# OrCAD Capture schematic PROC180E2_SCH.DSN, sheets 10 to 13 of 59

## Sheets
10 21. SOC RESET - 1: size C; title: SOC  RESET - 1
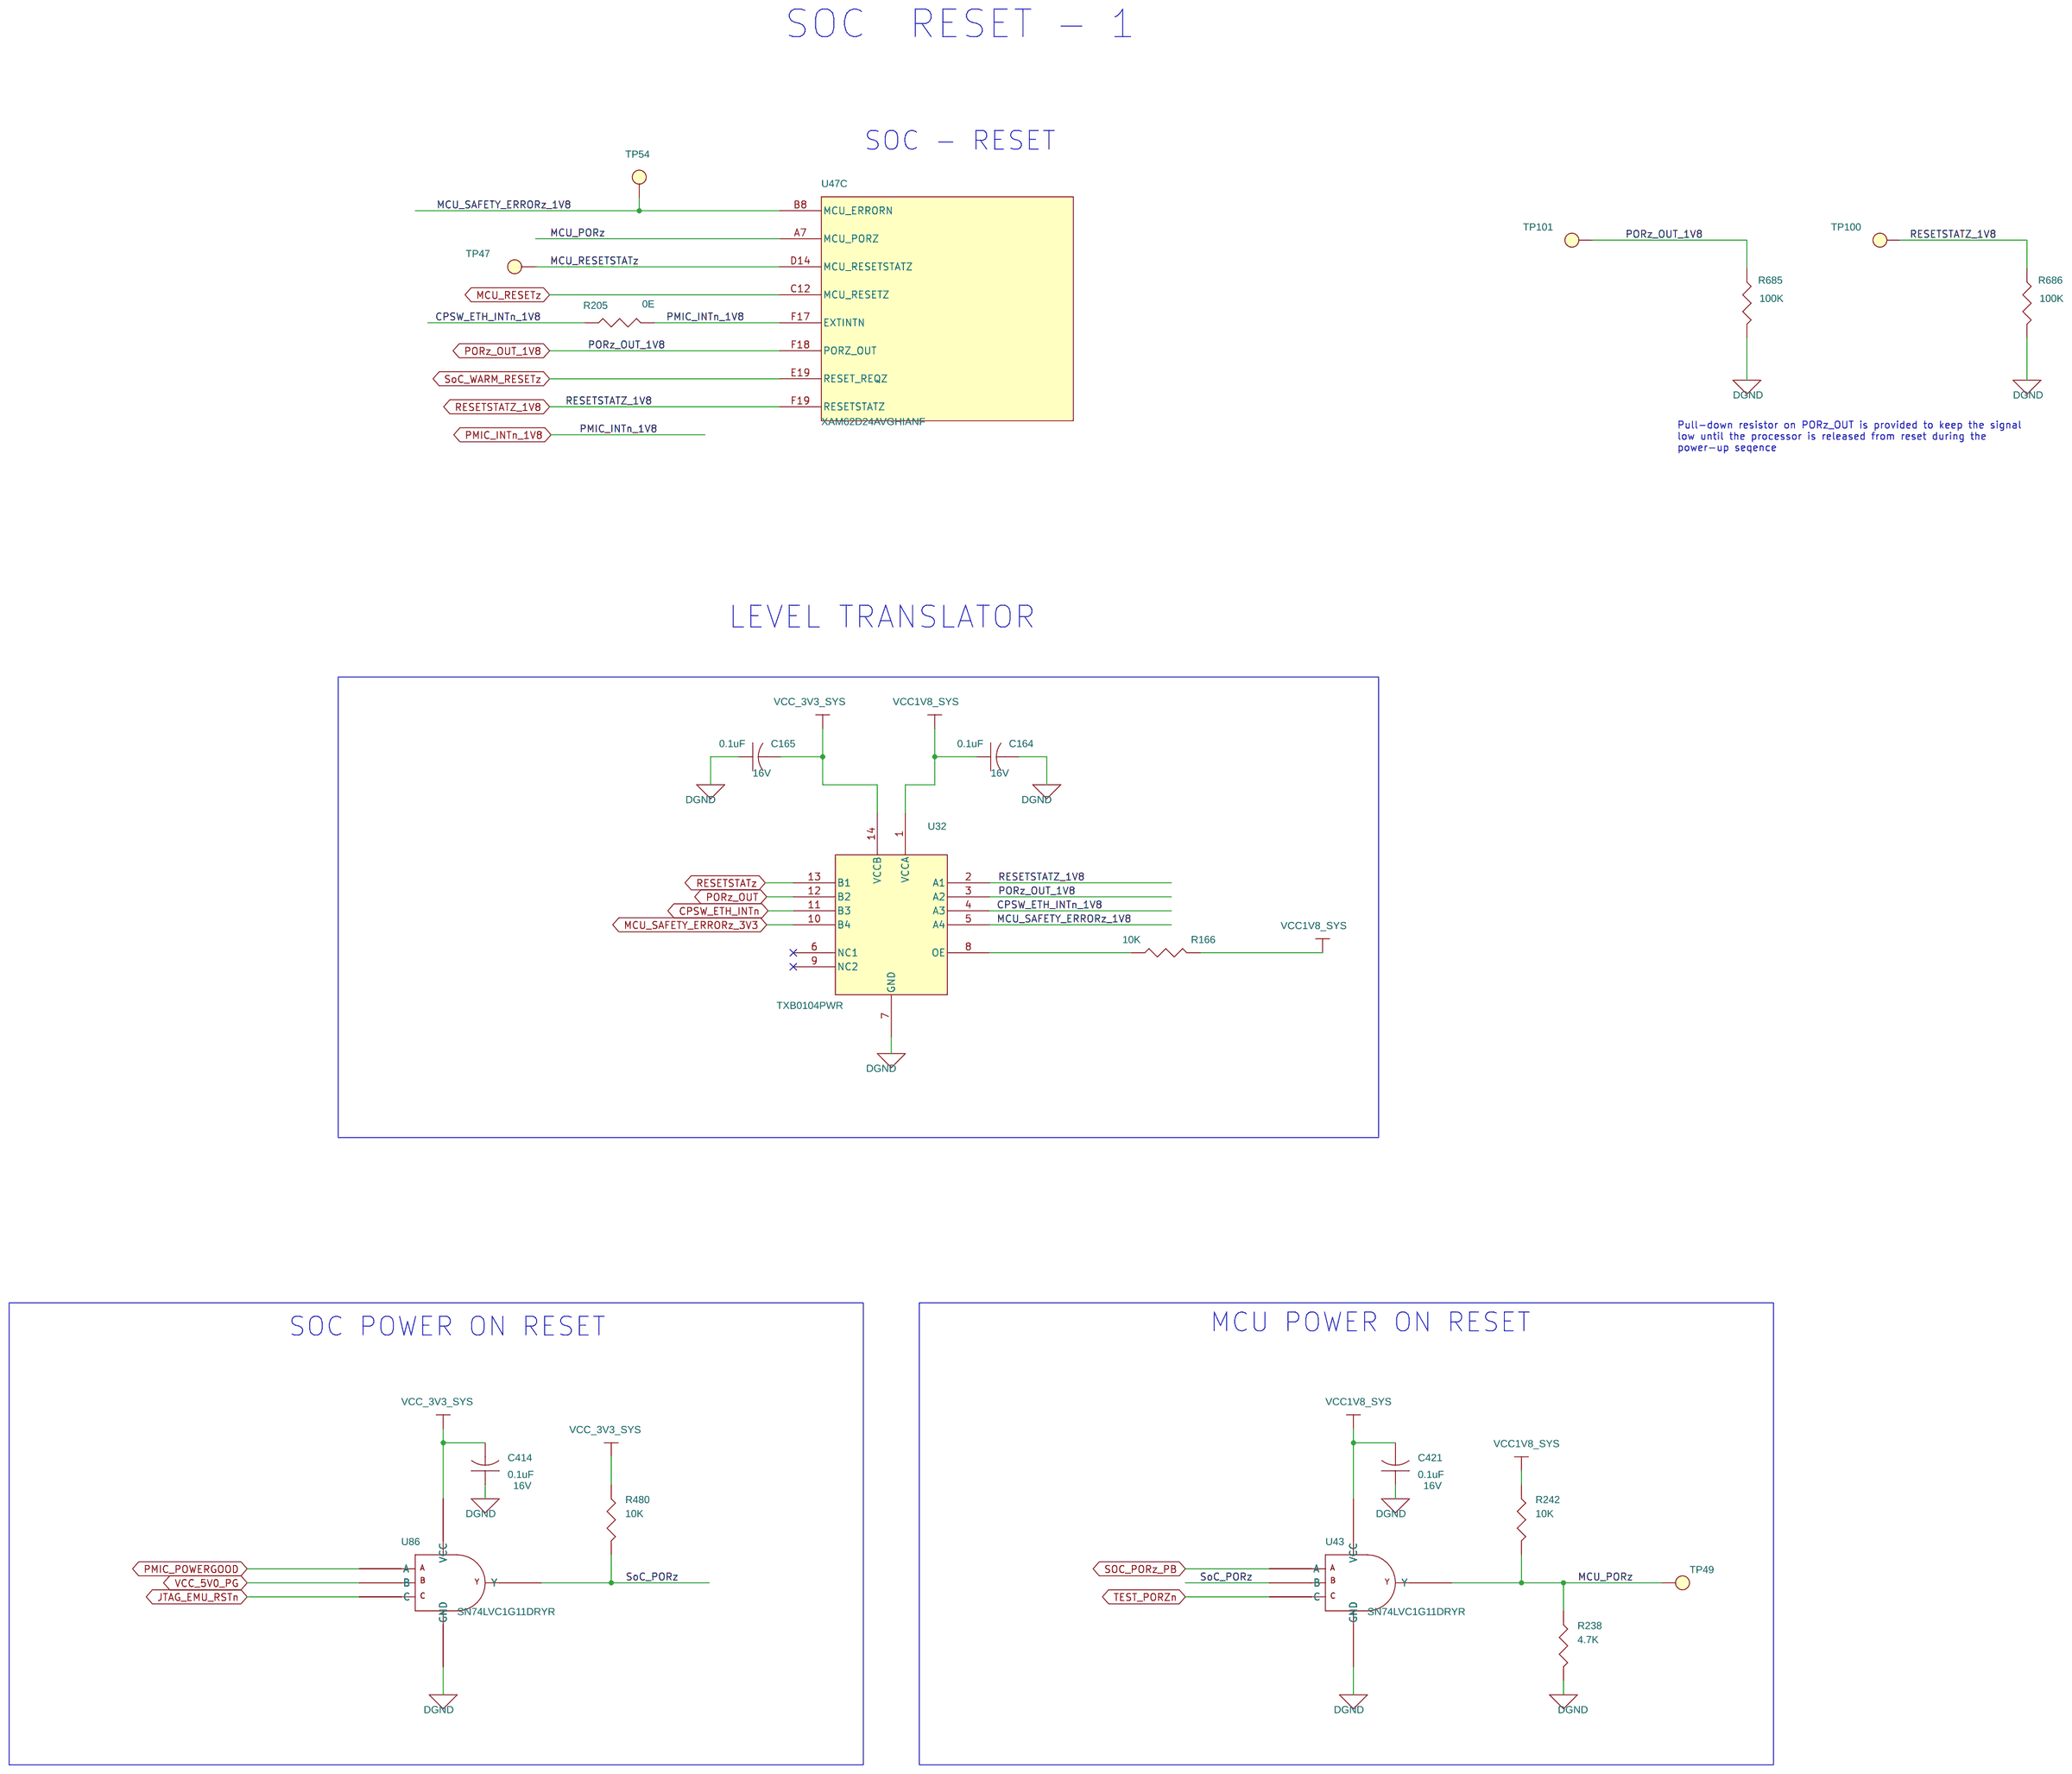
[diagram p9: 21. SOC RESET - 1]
11 28. SOC PERIPHERALS 1: size C; title: SOC PERIPHERALS 1
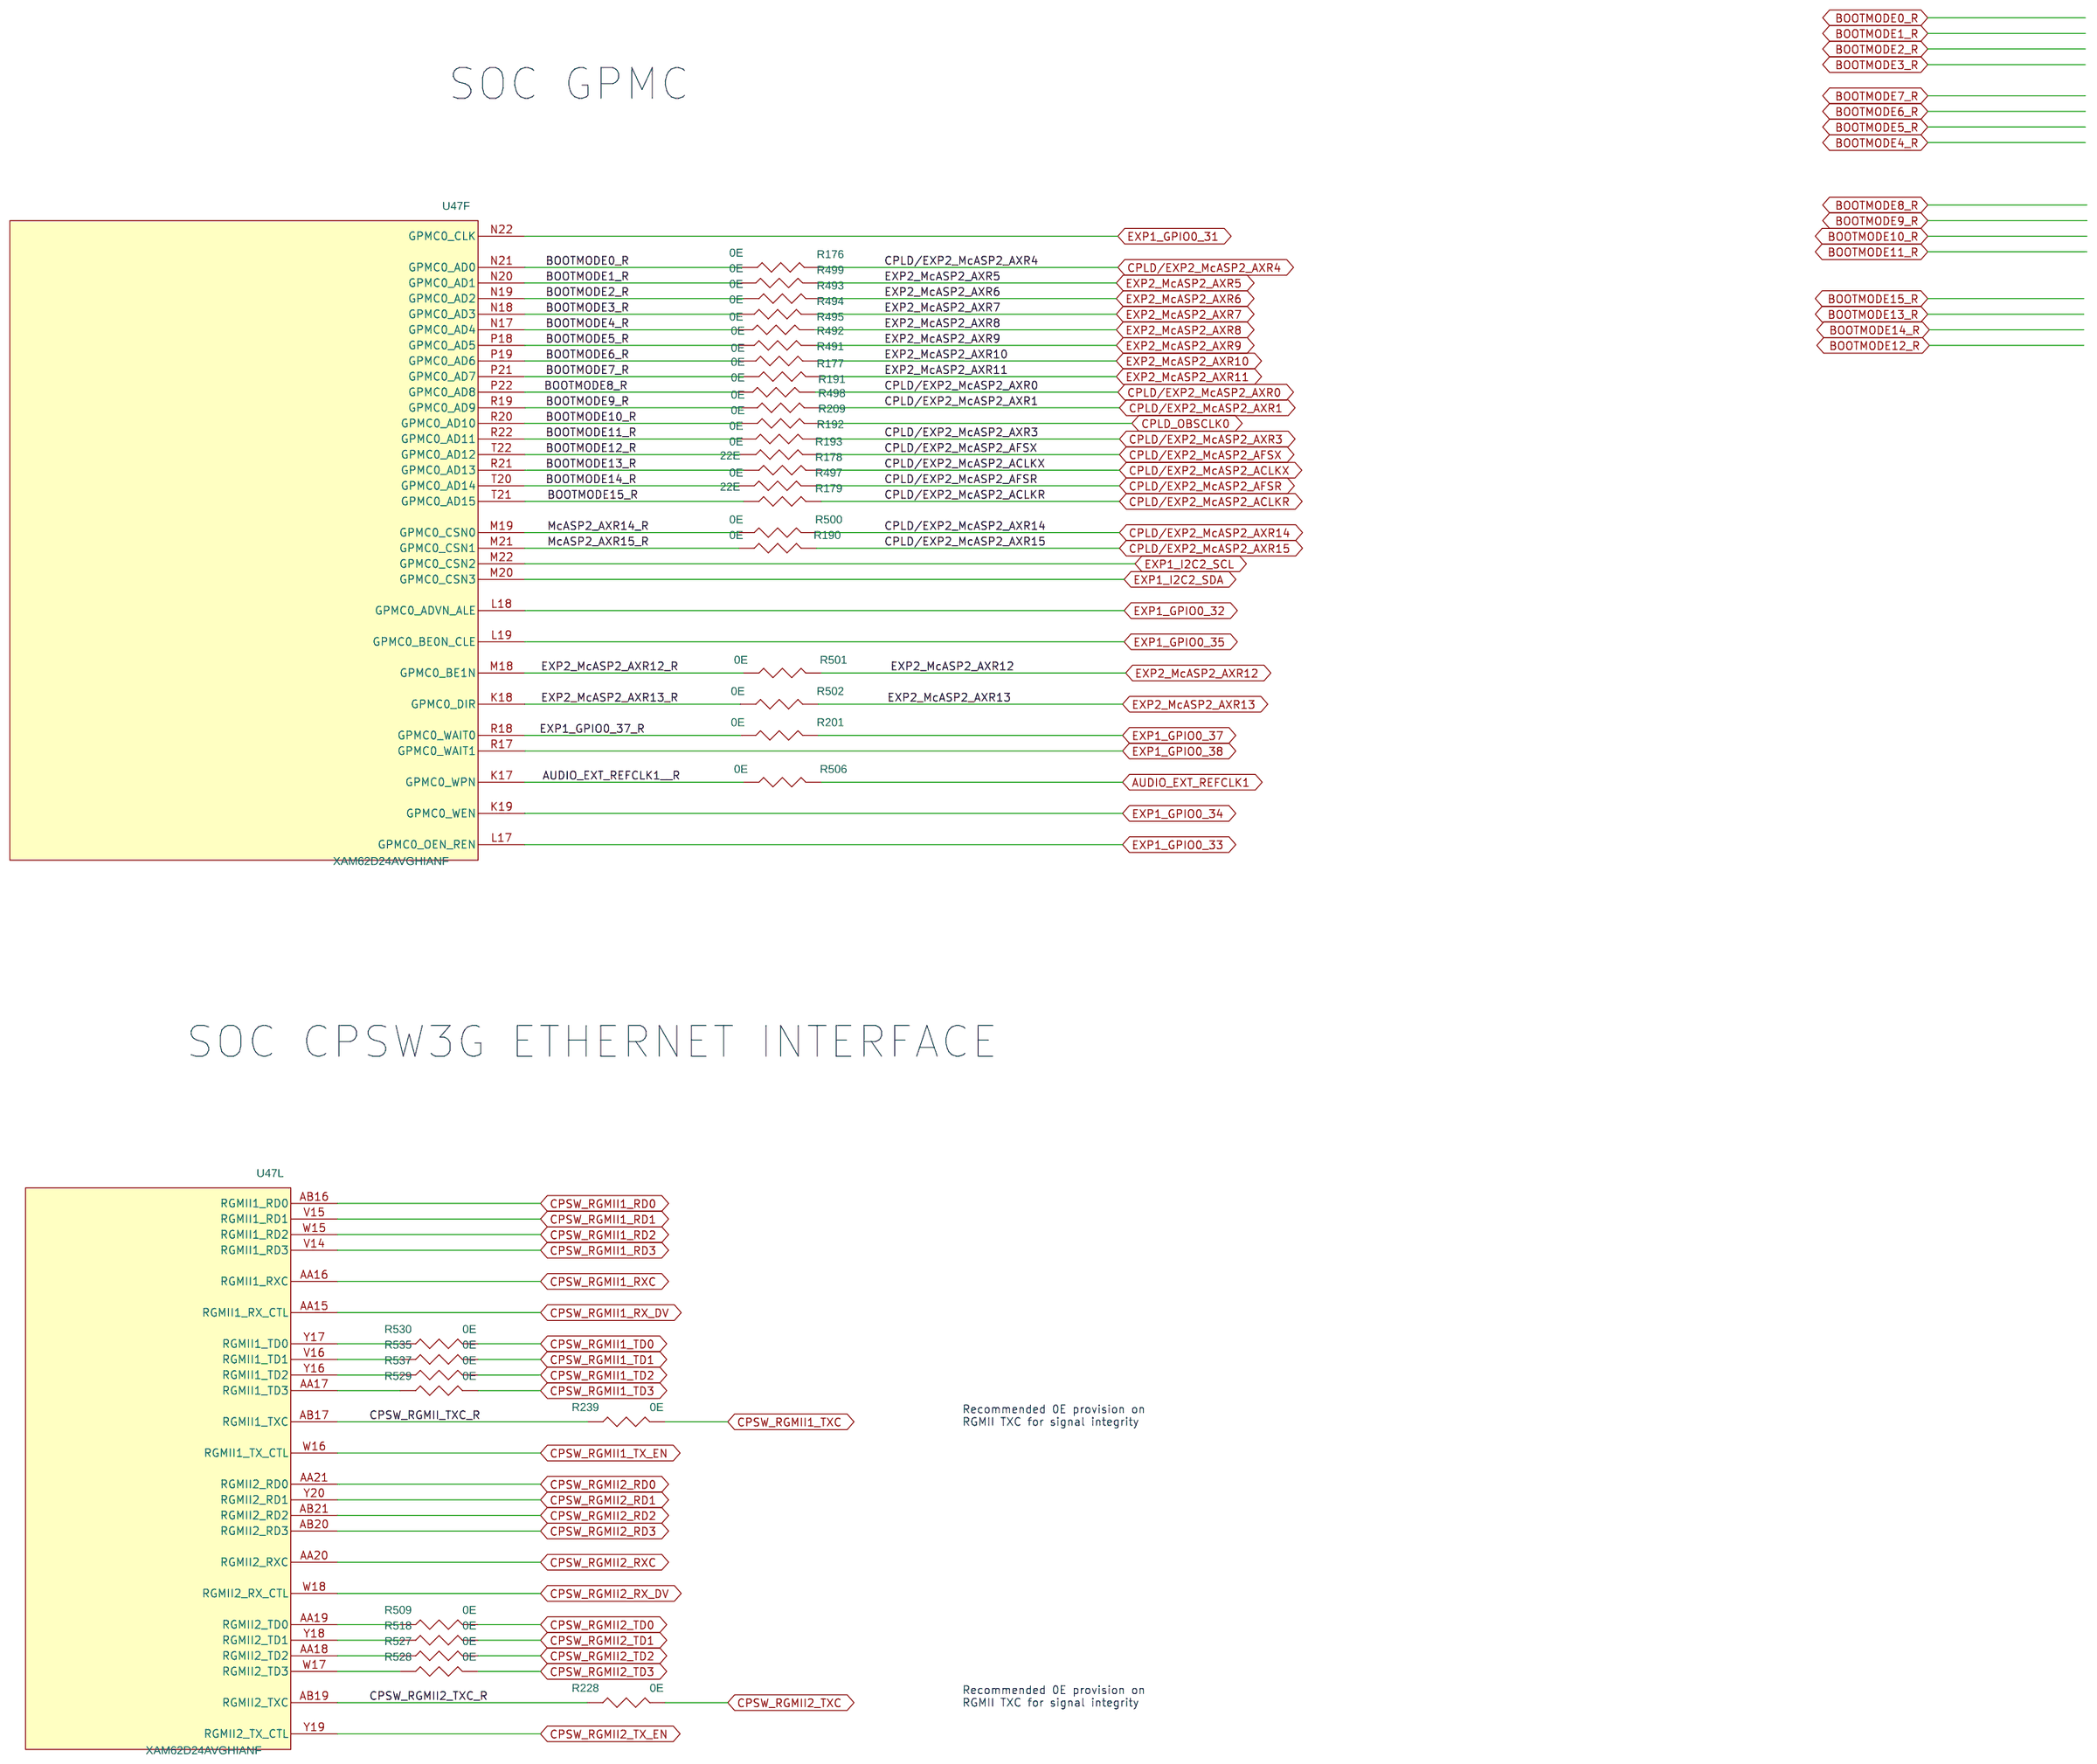
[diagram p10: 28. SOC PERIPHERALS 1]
12 11. USB TYPE-C POWER CONNECTOR: size C; title: USB TYPE-C POWER CONNECTOR
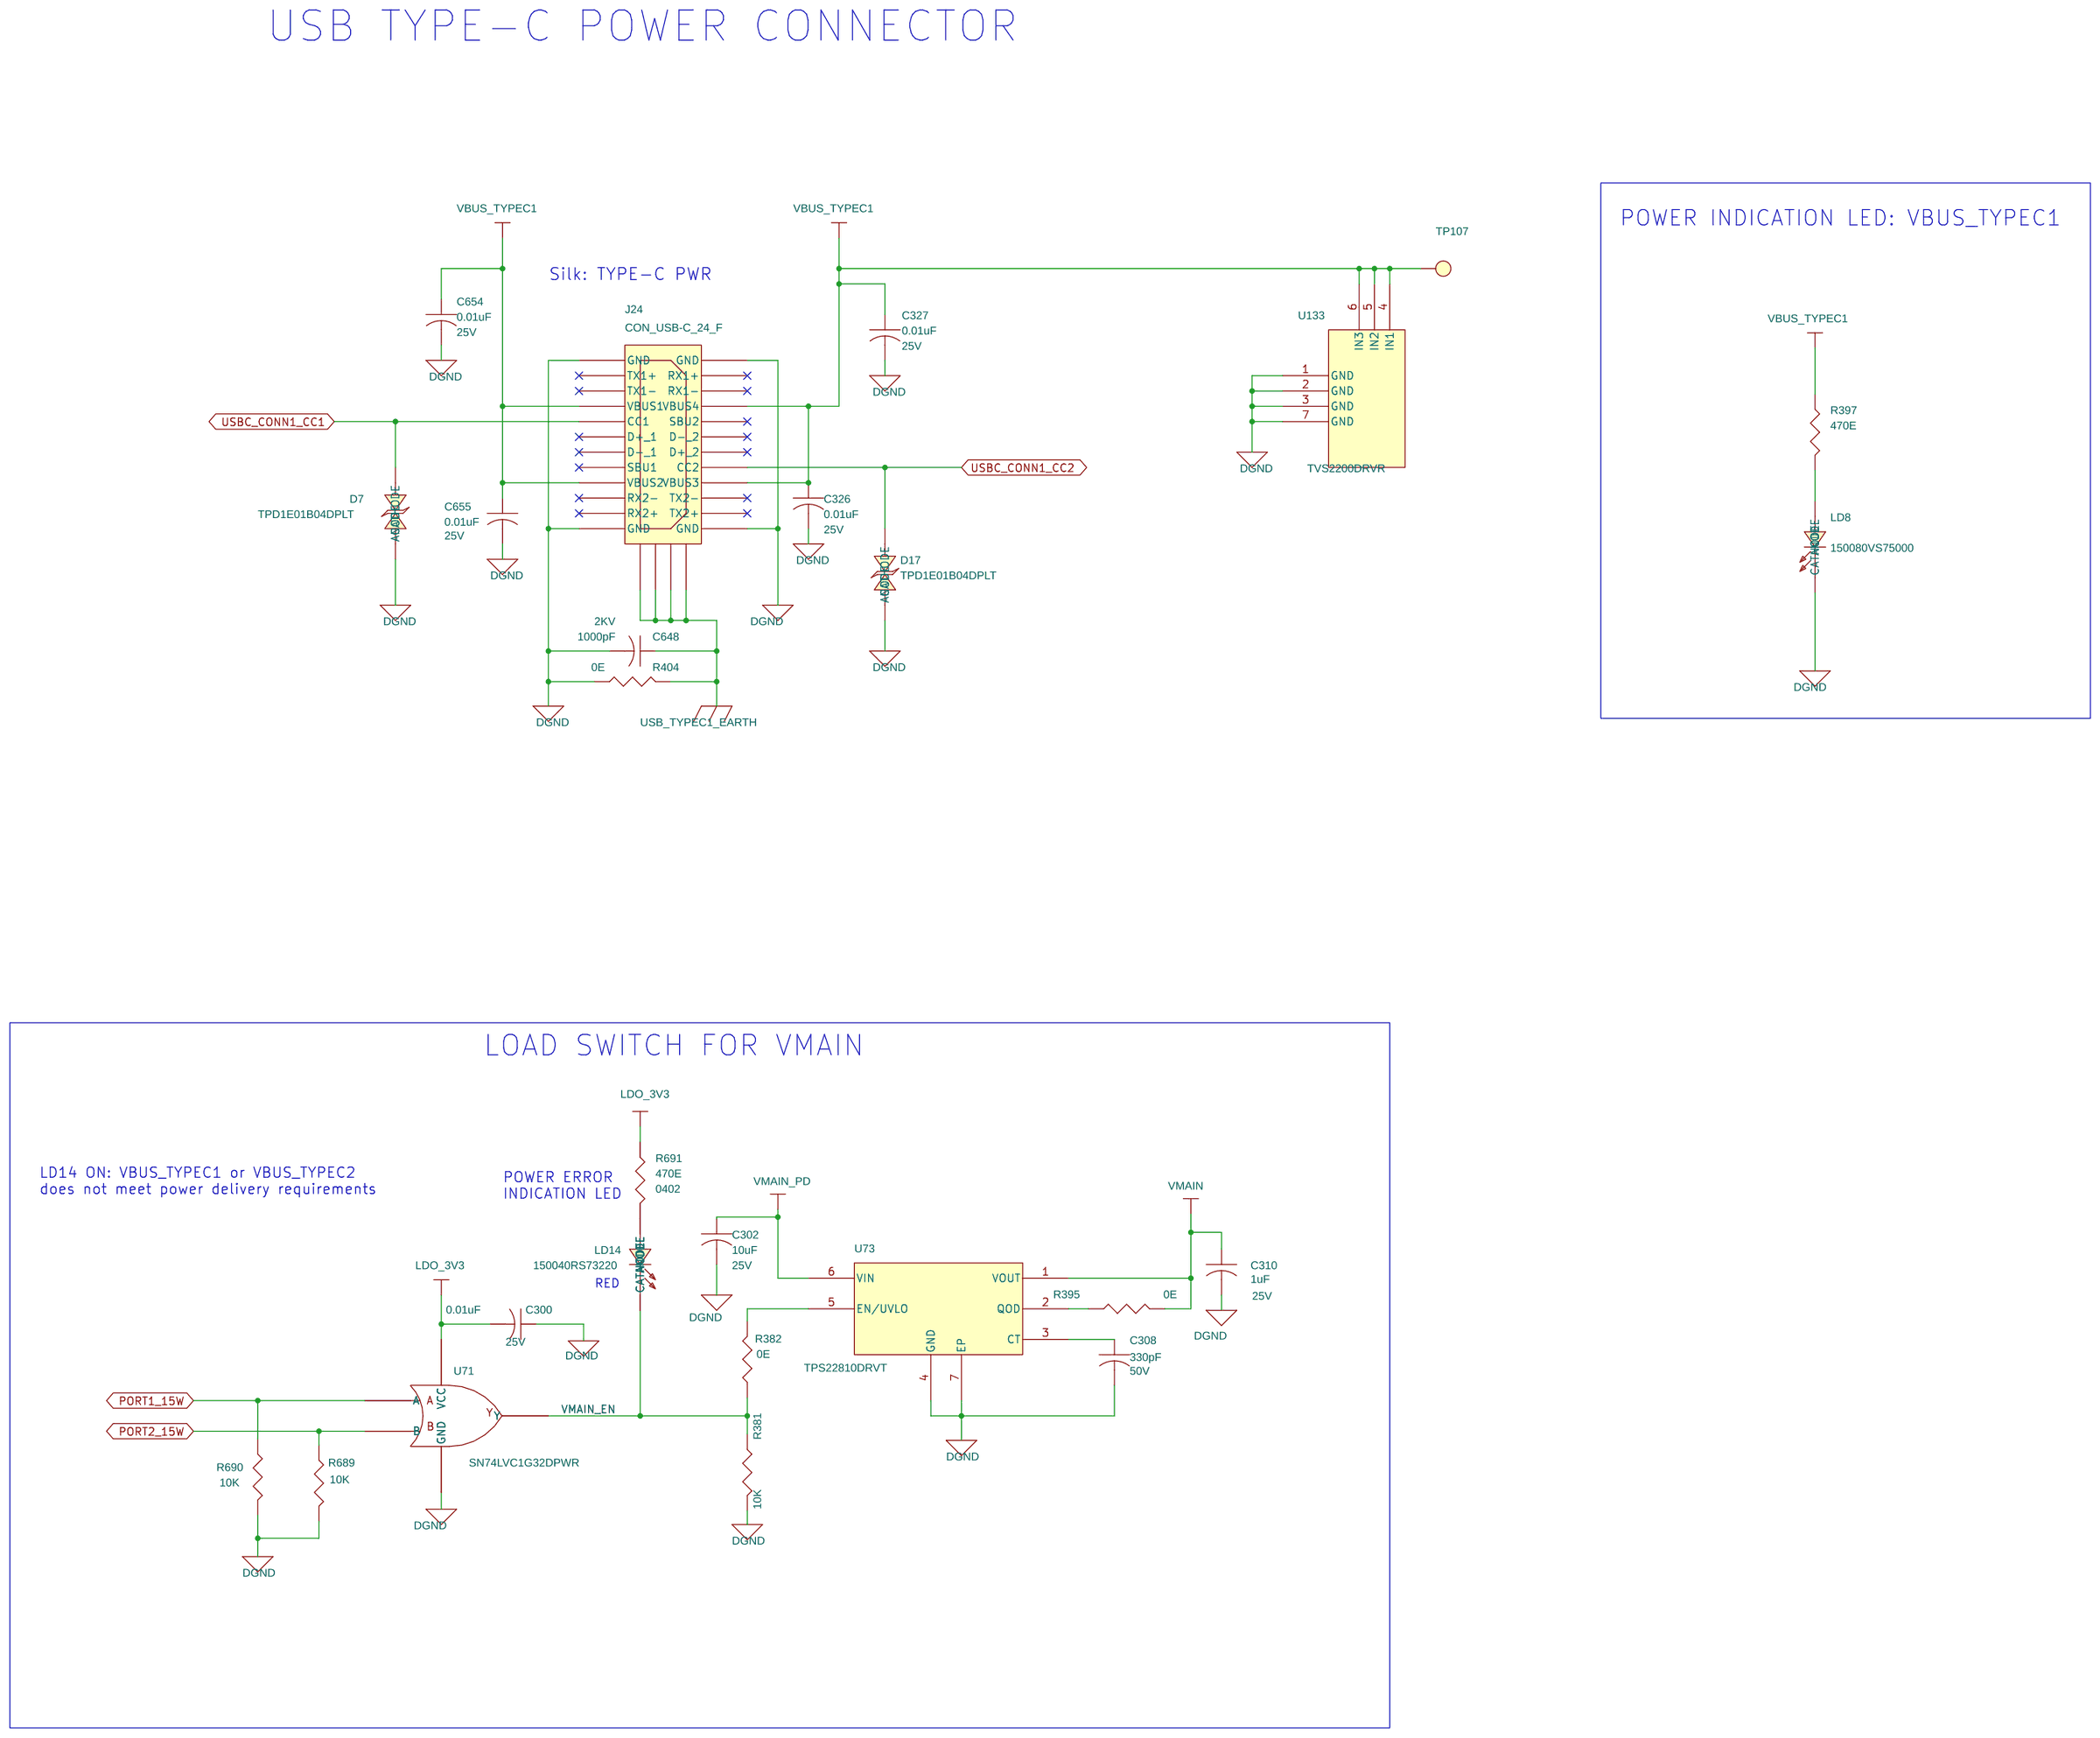
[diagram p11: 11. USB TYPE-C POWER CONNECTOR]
13 18. SOC POWER SUPPLIES - DECAPS: size C; title: SOC POWER SUPPLIES - DECAPS 2
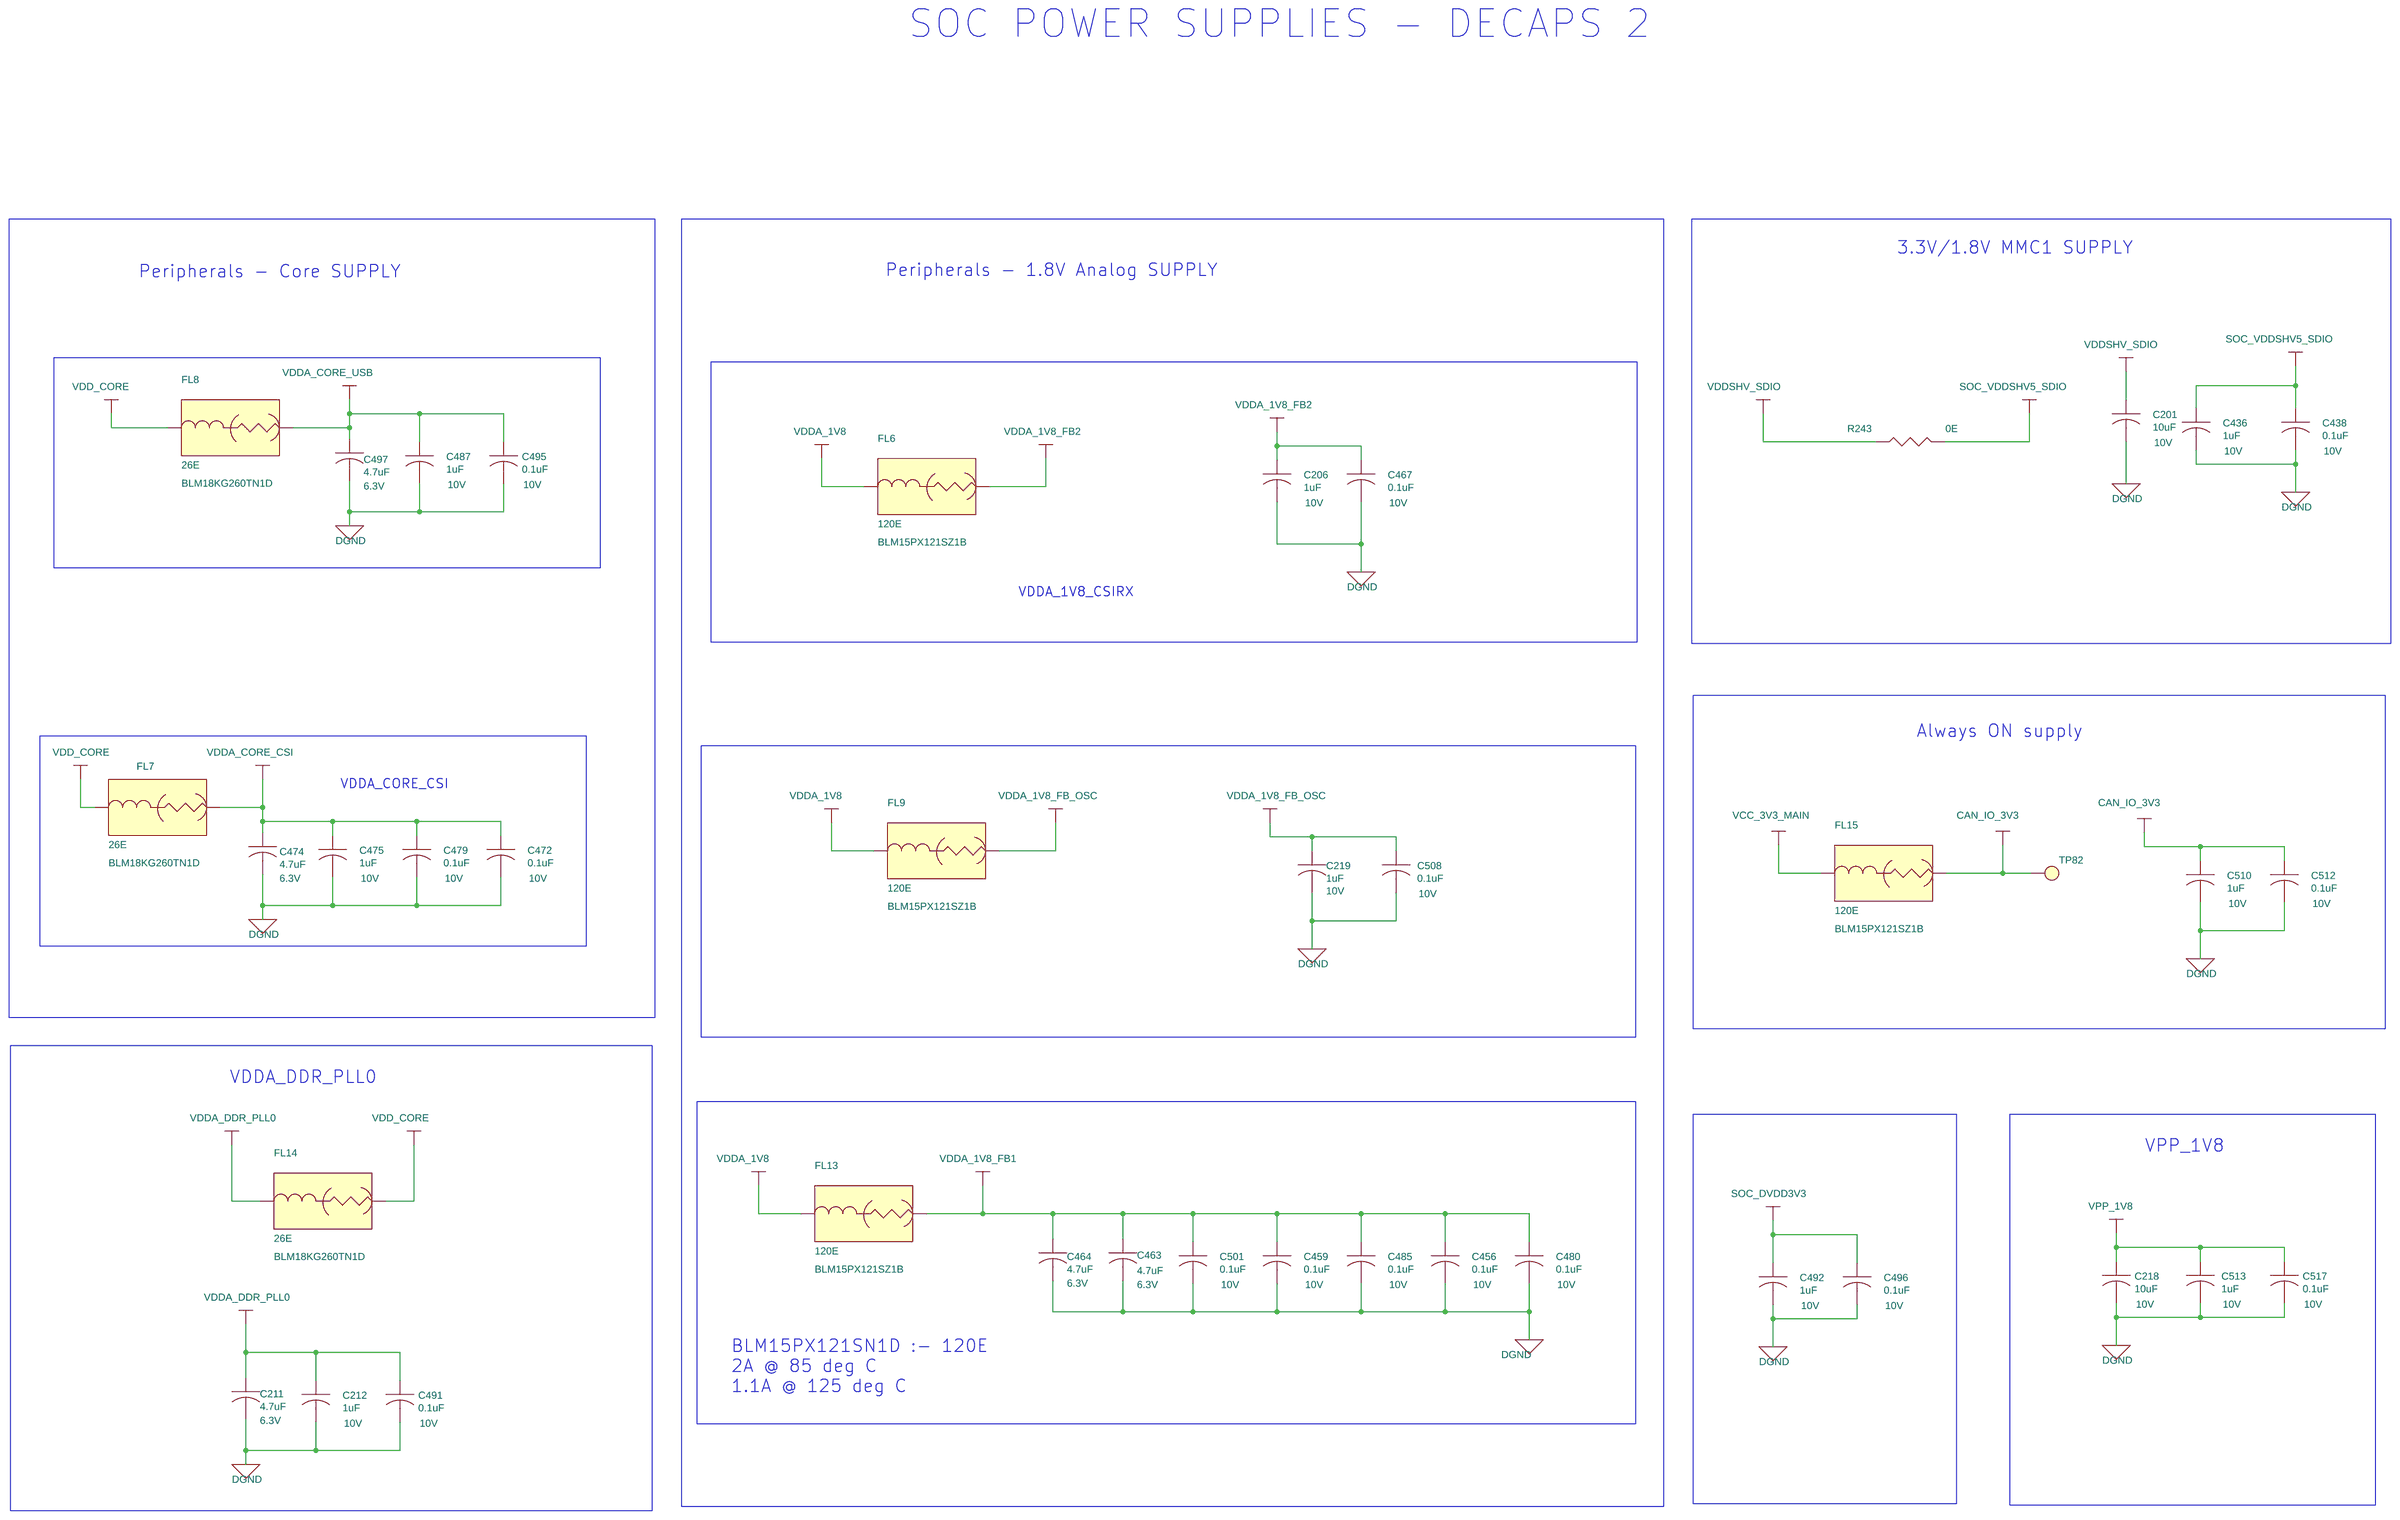
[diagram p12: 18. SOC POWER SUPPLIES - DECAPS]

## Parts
sheet 11. USB TYPE-C POWER CONNECTOR
C300  0.01uF  [CAP0201_0-5]
C302  10uF  [CAP0603_1]
C308  330pF  [CAP0402_0-75]
C310  1uF  [CAP0402_0-75]
C326  0.01uF  [CAP0201_0-5]
C327  0.01uF  [CAP0201_0-5]
C648  1000pF  [CAP1206_1-75]
C654  0.01uF  [CAP0201_0-5]
C655  0.01uF  [CAP0201_0-5]
D7  TPD1E01B04DPLT  [DIO_DFN0201_0-4]
D17  TPD1E01B04DPLT  [DIO_DFN0201_0-4]
J24  CON_USB-C_24_F  [CON_USBC24_2012670_S_R_S_3-9]
LD8  150080VS75000  [LED_150080VS75000_80X50_SMD_0-8]
LD14  150040RS73220  [LED_150040GS73220_40X20_SMD_0-4]
R381  10K  [RES0201_0-5]
R382  0E  [RES0201_0-5]
R395  0E  [RES0603_0-75]
R397  470E  [RES0402_0-5]
R404  0E  [RES0603_0-75]
R689  10K  [RES0201_0-5]
R690  10K  [RES0201_0-5]
R691  470E  [RES0402_0-5]
TP107  TP20_SMD  [TP20_SMD]
U71  SN74LVC1G32DPWR  [X2SON5_TLV7021_30X30_0-4]
U73  TPS22810DRVT  [SON6_25-59_85X85_0-8]
U133  TVS2200DRVR  [SON6_25-59_85X85_0-8]
sheet 18. SOC POWER SUPPLIES - DECAPS
C201  10uF  [CAP0402_1]
C206  1uF  [CAP0201_0-5]
C211  4.7uF  [CAP0201_0-5]
C212  1uF  [CAP0201_0-5]
C218  10uF  [CAP0402_1]
C219  1uF  [CAP0201_0-5]
C436  1uF  [CAP0201_0-5]
C438  0.1uF  [CAP0201_0-5]
C456  0.1uF  [CAP0201_0-5]
C459  0.1uF  [CAP0201_0-5]
C463  4.7uF  [CAP0201_0-5]
C464  4.7uF  [CAP0201_0-5]
C467  0.1uF  [CAP0201_0-5]
C472  0.1uF  [CAP0201_0-5]
C474  4.7uF  [CAP0201_0-5]
C475  1uF  [CAP0201_0-5]
C479  0.1uF  [CAP0201_0-5]
C480  0.1uF  [CAP0201_0-5]
C485  0.1uF  [CAP0201_0-5]
C487  1uF  [CAP0201_0-5]
C491  0.1uF  [CAP0201_0-5]
C492  1uF  [CAP0201_0-5]
C495  0.1uF  [CAP0201_0-5]
C496  0.1uF  [CAP0201_0-5]
C497  4.7uF  [CAP0201_0-5]
C501  0.1uF  [CAP0201_0-5]
C508  0.1uF  [CAP0201_0-5]
C510  1uF  [CAP0201_0-5]
C512  0.1uF  [CAP0201_0-5]
C513  1uF  [CAP0201_0-5]
C517  0.1uF  [CAP0201_0-5]
FL6  120E  [EMIFIL_BLM15A_0402_0-6]
FL7  26E  [EMIFIL_BLM18K_0603]
FL8  26E  [EMIFIL_BLM18K_0603]
FL9  120E  [EMIFIL_BLM15A_0402_0-6]
FL13  120E  [EMIFIL_BLM15A_0402_0-6]
FL14  26E  [EMIFIL_BLM18K_0603]
FL15  120E  [EMIFIL_BLM15A_0402_0-6]
R243  0E  [RES0402_0-5]
TP82  TP20_SMD  [TP20_SMD]
sheet 21. SOC RESET - 1
C164  0.1uF  [CAP0201_0-5]
C165  0.1uF  [CAP0201_0-5]
C414  0.1uF  [CAP0201_0-5]
C421  0.1uF  [CAP0201_0-5]
R166  10K  [RES0201_0-5]
R205  0E  [RES0201_0-5]
R238  4.7K  [RES0201_0-5]
R242  10K  [RES0201_0-5]
R480  10K  [RES0201_0-5]
R685  100K  [RES0201_0-5]
R686  100K  [RES0201_0-5]
TP47  TP20_SMD  [TP20_SMD]
TP49  TP20_SMD  [TP20_SMD]
TP54  TP20_SMD  [TP20_SMD]
TP100  TP20_SMD  [TP20_SMD]
TP101  TP20_SMD  [TP20_SMD]
U32  TXB0104PWR  [TSSOP14_25-59_205X180_1-2]
U43  SN74LVC1G11DRYR  [SON6_SN74LVC2G17_40X60_0-6]
U47  XAM62D24AVGHIANF  [FBGA484_31-49_710X710_2-7]  (sections A,B,C,D,E,F,G,H,I,J,K,L,M,N,O,P,Q)
U86  SN74LVC1G11DRYR  [SON6_SN74LVC2G17_40X60_0-6]
sheet 28. SOC PERIPHERALS 1
R176  0E  [RES0402_0-5]
R177  0E  [RES0402_0-5]
R178  22E  [RES0402_0-5]
R179  22E  [RES0402_0-5]
R190  0E  [RES0402_0-5]
R191  0E  [RES0402_0-5]
R192  0E  [RES0402_0-5]
R193  0E  [RES0402_0-5]
R201  0E  [RES0402_0-5]
R209  0E  [RES0402_0-5]
R228  0E  [RES0201_0-5]
R239  0E  [RES0201_0-5]
R491  0E  [RES0402_0-5]
R492  0E  [RES0402_0-5]
R493  0E  [RES0402_0-5]
R494  0E  [RES0402_0-5]
R495  0E  [RES0402_0-5]
R497  0E  [RES0402_0-5]
R498  0E  [RES0402_0-5]
R499  0E  [RES0402_0-5]
R500  0E  [RES0402_0-5]
R501  0E  [RES0402_0-5]
R502  0E  [RES0402_0-5]
R506  0E  [RES0402_0-5]
R509  0E  [RES0201_0-5]
R518  0E  [RES0201_0-5]
R527  0E  [RES0201_0-5]
R528  0E  [RES0201_0-5]
R529  0E  [RES0201_0-5]
R530  0E  [RES0201_0-5]
R535  0E  [RES0201_0-5]
R537  0E  [RES0201_0-5]

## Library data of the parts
C300 C326 C327 C654 C655 = CAP: CAP CERAMIC 0.01uF 25V 10% X5R AUTO 0201; Chkd/date: MANIRAJA/311221; Crtd /date: ALVY/301221; Custom_Duty: 15%; Customs_HS_Code: 85322990; Distributor_name: MOUSER; Distributor_part_number: 81-GRT033R61E103KE1D; Footprint Path: Y:\MIS_DATABASE\Library\ALTIUM_TOOL\PCB_FOOTPRINTS\Altium_Footprint_Lib.PcbLib; Height: 0.33MM; Library Path: Y:\MIS_DATABASE\Library\ALTIUM_TOOL\SCHEMATICS_PARTS\MS_DISCRETE_Library.schlib; Mfr_name: MURATA; Mfr_part_number: GRT033R61E103KE01D; Mistral Part No: 120021120019-R; Package: 0201; Part_type: CAPACITORS\CERAMIC; Project: AM62Q_SKEVM_BRD; RoHS: RoHS; Temperature: -55°C+85°C; Tolerance: 10%; Voltage: 25V; Wattage: NA; Weight: 0.33mg; Datasheet: Y:\MIS_DATABASE\DATASHEETS\CAPACITORS\GRT033R61E103KE01.PDF
C302 = CAP: CAP CERAMIC 10uF 25V 20% X5R AUTO 0603; Chkd/date: PRADEEP/130623; Crtd /date: PRADEEP/130623; Custom_Duty: 15%; Customs_HS_Code: 85322990; Distributor_name: NA; Distributor_part_number: NA; Footprint Path: Y:\MIS_DATABASE\Library\ALTIUM_TOOL\PCB_FOOTPRINTS\Altium_Footprint_Lib.PcbLib; Height: 1.00MM; Library Path: Y:\MIS_DATABASE\Library\ALTIUM_TOOL\SCHEMATICS_PARTS\MS_DISCRETE_Library.schlib; Mfr_name: MURATA; Mfr_part_number: GRT188R61E106ME13; Mistral Part No: 120022060023-R; Package: 0603; Part_type: CAPACITORS\CERAMIC; Project: AM62P_SK; RoHS: RoHS; Temperature: -55°C+85°C; Tolerance: 20%; Voltage: 25V; Wattage: NA; Weight: 2mg; Datasheet: Y:\MIS_DATABASE\DATASHEETS\CAPACITORS\GRT188R61E106ME13.PDF
C308 = CAP: CAP CERAMIC 330pF 50V 5% C0G(NP0) AUTO 0402; Chkd/date: MANIRAJA/250221; Crtd /date: ALVY/240221; Custom_Duty: 15%; Customs_HS_Code: 85322990; Distributor_name: MOUSER; Distributor_part_number: 81-GRT1555C1H331JA2D; Footprint Path: Y:\MIS_DATABASE\Library\ALTIUM_TOOL\PCB_FOOTPRINTS\Altium_Footprint_Lib.PcbLib; Height: 0.55MM; Library Path: Y:\MIS_DATABASE\Library\ALTIUM_TOOL\SCHEMATICS_PARTS\MS_DISCRETE_Library.schlib; Mfr_name: MURATA; Mfr_part_number: GRT1555C1H331JA02D; Mistral Part No: 120019050019-R; Package: 0402; Part_type: CAPACITORS\CERAMIC; Project: TI_DRA821 SK EVM BRD; RoHS: RoHS; Temperature: -55°C+125°C; Tolerance: 5%; Voltage: 50V; Wattage: NA; Weight: 3.1mg; Datasheet: Y:\MIS_DATABASE\DATASHEETS\CAPACITORS\GRT1555C1H331JA02.PDF
C310 = CAP: CAP CERAMIC 1uF 25V 10% X6S AUTO 0402; Chkd/date: MANIRAJA/270520; Crtd /date: ALVY/260520; Custom_Duty: 15%; Customs_HS_Code: 85322990; Distributor_name: DIGIKEY; Distributor_part_number: 490-18215-1-ND; Footprint Path: Y:\MIS_DATABASE\Library\ALTIUM_TOOL\PCB_FOOTPRINTS\Altium_Footprint_Lib.PcbLib; Height: 0.60MM; Library Path: Y:\MIS_DATABASE\Library\ALTIUM_TOOL\SCHEMATICS_PARTS\MS_DISCRETE_Library.schlib; Mfr_name: MURATA; Mfr_part_number: GRT155C81E105KE13D; Mistral Part No: 120020050024-R; Package: 0402; Part_type: CAPACITORS\CERAMIC; Project: DARE_ECU_MCB; RoHS: RoHS; Temperature: -55°C+105°C; Tolerance: 10%; Voltage: 25V; Wattage: NA; Weight: 1.6mg; Datasheet: Y:\MIS_DATABASE\DATASHEETS\CAPACITORS\GRT155C81E105KE13.PDF
C648 = CAP: CAP CERAMIC 1000pF 2KV 10% X7R 1206; Chkd/date: SHREESHAIL/291106; Crtd /date: MAZHAR/281106; Custom_Duty: 15%; Customs_HS_Code: 85322990; Distributor_name: DIGIKEY; Distributor_part_number: 478-2956-1-ND; Footprint Path: Y:\MIS_DATABASE\Library\ALTIUM_TOOL\PCB_FOOTPRINTS\Altium_Footprint_Lib.PcbLib; Height: 1.52MM; Library Path: Y:\MIS_DATABASE\Library\ALTIUM_TOOL\SCHEMATICS_PARTS\MS_DISCRETE_Library.schlib; Mfr_name: AVX CORPORATION; Mfr_part_number: 1206GC102KAT1A; Mistral Part No: 120015080006-R; Package: 1206; Part_type: CAPACITORS\CERAMIC; Project: ADR1B; RoHS: RoHS; Temperature: -55°C+125°C; Tolerance: 10%; Voltage: 2KV; Wattage: NA; Weight: 16.2mg; Datasheet: Y:\MIS_DATABASE\DATASHEETS\CAPACITORS\AVX_HV-MLC.PDF
D7 D17 = DIODE_TVS_DUAL: DIODE 1CH ESD PROTECTION FOR USB TYPE-C AND THUNDERBOLT3 X2SON2; Chkd/date: MANIRAJA/230920; Crtd /date: ALVY/230920; Custom_Duty: 15%; Customs_HS_Code: 85412900; Distributor_name: DIGIKEY; Distributor_part_number: 296-44484-1-ND; Footprint Path: Y:\MIS_DATABASE\Library\ALTIUM_TOOL\PCB_FOOTPRINTS\Altium_Footprint_Lib.PcbLib; Height: 0.32MM; Library Path: Y:\MIS_DATABASE\Library\ALTIUM_TOOL\SCHEMATICS_PARTS\MS_DISCRETE_Library.schlib; Mfr_name: TEXAS INSTRUMENTS; Mistral Part No: 130020090037-R; Package: X2SON2; Part_type: DIODE\TVS; Project: AM64X_SKEVM; RoHS: RoHS; Temperature: -40°C+125°C; Tolerance: NA; Voltage: NA; Wattage: NA; Weight: 0.2mg; Datasheet: Y:\MIS_DATABASE\DATASHEETS\DISCRETES\DIODES\TPD1E01B04.PDF
J24 = CON_USB-C_24_1240183621: CON USB-C TYPE 24POS FEMALE RT SMD; Chkd/date: MANIRAJA/050618; Crtd /date: ALVY/040618; Custom_Duty: 24%; Customs_HS_Code: 85369090; Distributor_name: DIGIKEY; Distributor_part_number: WM17992CT-ND; Footprint Path: Y:\MIS_DATABASE\Library\ALTIUM_TOOL\PCB_FOOTPRINTS\Altium_Footprint_Lib.PcbLib; Height: 3.86MM; Library Path: Y:\MIS_DATABASE\Library\ALTIUM_TOOL\SCHEMATICS_PARTS\MS_CONNECTOR_Library.schlib; Mfr_name: MOLEX; Mfr_part_number: 2012670005; Mistral Part No: 150018060002-R; Package: SMD; Part_type: CONNECTOR\USB; Project: TI_J7SVB_USB_ADD-ON-CARD; RoHS: RoHS; Temperature: -40°C+105°C; Tolerance: NA; Voltage: NA; Wattage: NA; Weight: 0.686g; Datasheet: Y:\MIS_DATABASE\DATASHEETS\CONNECTORS\2012670X.PDF
LD8 = DIODE_LED: DIODE LED BRIGHT GREEN SMD; Chkd/date: MANIRAJA/180820; Crtd /date: ALVY/180820; Custom_Duty: 24%; Customs_HS_Code: 85439000; Distributor_name: DIGIKEY; Distributor_part_number: 732-4986-1-ND; Footprint Path: Y:\MIS_DATABASE\Library\ALTIUM_TOOL\PCB_FOOTPRINTS\Altium_Footprint_Lib.PcbLib; Height: 0.80MM; Library Path: Y:\MIS_DATABASE\Library\ALTIUM_TOOL\SCHEMATICS_PARTS\MS_OPTO_Library.schlib; Mfr_name: WURTH ELECTRONICS; Mistral Part No: 130020080012-R; Package: SMD; Part_type: OPTO\LED; Project: AM64x_EVM_BRD; RoHS: RoHS; Temperature: -40°C+85°C; Tolerance: NA; Voltage: NA; Wattage: NA; Weight: 10mg; Datasheet: Y:\MIS_DATABASE\DATASHEETS\DISCRETES\LEDS\150080VS75000.PDF
LD14 = DIODE_LED: DIODE LED RED SMD; Chkd/date: MANIRAJA/100920; Crtd /date: ALVY/100920; Custom_Duty: 24%; Customs_HS_Code: 85439000; Distributor_name: DIGIKEY; Distributor_part_number: 732-13422-1-ND; Footprint Path: Y:\MIS_DATABASE\Library\ALTIUM_TOOL\PCB_FOOTPRINTS\Altium_Footprint_Lib.PcbLib; Height: 0.35MM; Library Path: Y:\MIS_DATABASE\Library\ALTIUM_TOOL\SCHEMATICS_PARTS\MS_OPTO_Library.schlib; Mfr_name: WURTH ELECTRONICS; Mistral Part No: 130020090020-R; Package: SMD; Part_type: OPTO\LED; Project: AM64X_SKEVM; RoHS: RoHS; Temperature: -40°C+85°C; Tolerance: NA; Voltage: NA; Wattage: NA; Weight: 29.3mg; Datasheet: Y:\MIS_DATABASE\DATASHEETS\DISCRETES\LEDS\150040RS73220.PDF
R166 R242 R381 R480 R689 R690 = RESISTOR: RES 10K 1/20W 5% 0201; Chkd/date: MANIRAJA/050517; Crtd /date: MANIRAJA/050517; Custom_Duty: 15%; Customs_HS_Code: 85332119; Distributor_name: DIGIKEY; Distributor_part_number: 311-10KNCT-ND; Footprint Path: Y:\MIS_DATABASE\Library\ALTIUM_TOOL\PCB_FOOTPRINTS\Altium_Footprint_Lib.PcbLib; Height: 0.26MM; Library Path: Y:\MIS_DATABASE\Library\ALTIUM_TOOL\SCHEMATICS_PARTS\MS_DISCRETE_Library.schlib; Mfr_name: YAGEO AMERICA; Mfr_part_number: RC0201JR-0710KL; Mistral Part No: 110010070051-R; Package: 0201; Part_type: RESISTORS\FIXED; Project: GOLDEN-I LITE; RoHS: RoHS; Temperature: -55°C+125°C; Tolerance: 5%; Voltage: NA; Wattage: 1/20W; Weight: 0.17mg; Datasheet: Y:\MIS_DATABASE\DATASHEETS\RESISTORS\RCXXXXL-SER_MAR18.PDF
R205 R382 = RESISTOR: RES 0E 1/20W 5% 0201; Chkd/date: NAVEED/301214; Crtd /date: MUDDU/120710; Custom_Duty: 15%; Customs_HS_Code: 85332119; Distributor_name: DIGIKEY; Distributor_part_number: 311-0.0NCT-ND; Footprint Path: Y:\MIS_DATABASE\Library\ALTIUM_TOOL\PCB_FOOTPRINTS\Altium_Footprint_Lib.PcbLib; Height: 0.26MM; Library Path: Y:\MIS_DATABASE\Library\ALTIUM_TOOL\SCHEMATICS_PARTS\MS_DISCRETE_Library.schlib; Mfr_name: YAGEO AMERICA; Mfr_part_number: RC0201JR-070RL; Mistral Part No: 110010070067-R; Package: 0201; Part_type: RESISTORS\FIXED; Project: PB_BUGBASE; RoHS: RoHS; Temperature: -55°C+125°C; Tolerance: 5%; Voltage: NA; Wattage: 1/20W; Weight: 0.17mg; Datasheet: Y:\MIS_DATABASE\DATASHEETS\RESISTORS\RCXXXXL-SER_MAR18.PDF
R395 R404 = RESISTOR: RES 0E 1/10W 5% 0603; Chkd/date: MANIRAJA/051217; Crtd /date: BAVISH/180211; Custom_Duty: 15%; Customs_HS_Code: 85332119; Distributor_name: DIGIKEY; Distributor_part_number: 311-0.0GRCT-ND; Footprint Path: Y:\MIS_DATABASE\Library\ALTIUM_TOOL\PCB_FOOTPRINTS\Altium_Footprint_Lib.PcbLib; Height: 0.55MM; Library Path: Y:\MIS_DATABASE\Library\ALTIUM_TOOL\SCHEMATICS_PARTS\MS_DISCRETE_Library.schlib; Manufacturer: YAGEO AMERICA; Mfr_name: PANASONIC-ECG; Mfr_part_number: RC0603JR-070RL; Mistral Part No: 110011020013-R; Package: 0603; Part_type: RESISTORS\FIXED; Project: KENNEL; RoHS: RoHS; Temperature: -55°C+155°C; Tolerance: 5%; Voltage: NA; Wattage: 1/10W; Weight: 2mg; Datasheet: Y:\MIS_DATABASE\DATASHEETS\RESISTORS\RCXXXXL-SER_MAR18.PDF
R397 R691 = RESISTOR: RES 470E 1/10W 5% 0402; Chkd/date: SHREESHAIL/24050; Crtd /date: MAZHAR/260706; Custom_Duty: 15%; Customs_HS_Code: 85332119; Distributor_name: DIGIKEY; Distributor_part_number: P470JCT-ND; Footprint Path: Y:\MIS_DATABASE\Library\ALTIUM_TOOL\PCB_FOOTPRINTS\Altium_Footprint_Lib.PcbLib; Height: 0.40MM; Library Path: Y:\MIS_DATABASE\Library\ALTIUM_TOOL\SCHEMATICS_PARTS\MS_DISCRETE_Library.schlib; Mfr_name: PANASONIC-ECG; Mfr_part_number: ERJ-2GEJ471X; Mistral Part No: 110009030859-R; Package: 0402; Part_type: RESISTORS\FIXED; Project: POWERBOX; RoHS: RoHS; Temperature: -55°C+155°C; Tolerance: 5%; Voltage: NA; Wattage: 1/10W; Weight: 0.8mg; Datasheet: Y:\MIS_DATABASE\DATASHEETS\RESISTORS\PAN-ERJSER_NOV17.PDF
TP47 TP49 TP54 TP82 TP100 TP101 TP107 = TESTPOINT: TESTPOINT CIR 20 SMD; Chkd/date: SHREESHAIL/171006; Crtd /date: MAZHAR/171006; Custom_Duty: NA; Customs_HS_Code: NA; Distributor_name: NA; Distributor_part_number: NA; Footprint Path: Y:\MIS_DATABASE\Library\ALTIUM_TOOL\PCB_FOOTPRINTS\Altium_Footprint_Lib.PcbLib; Height: NA; Library Path: Y:\MIS_DATABASE\Library\ALTIUM_TOOL\SCHEMATICS_PARTS\MS_DISCRETE_Library.schlib; MECHANICAL 3D STEP FILE: NA; Mfr_name: LOCAL; Mistral Part No: NA; Package: SMD; Project: BT MODULE_CSRBC04; RoHS: NA; Temperature: NA; Tolerance: NA; Voltage: NA; Wattage: NA; Weight: NA; Datasheet: NA
U71 = SN74LVC1G32_X2SON5: IC SINGLE 2-INPUT POSITIVE-OR GATE X2SON5; Chkd/date: MANIRAJA/141020; Crtd /date: ALVY/131020; Custom_Duty: 15%; Customs_HS_Code: 85423100; Distributor_name: DIGIKEY; Distributor_part_number: 296-SN74LVC1G32DPWRCT-ND; Footprint Path: Y:\MIS_DATABASE\Library\ALTIUM_TOOL\PCB_FOOTPRINTS\Altium_Footprint_Lib.PcbLib; Height: 0.40MM; Library Path: Y:\MIS_DATABASE\Library\ALTIUM_TOOL\SCHEMATICS_PARTS\MS_GATE_Library.schlib; Mfr_name: TEXAS INSTRUMENTS; Mistral Part No: 141020100011-R; Package: X2SON5; Part_type: ICS\DIGITAL\GATES; Project: AM64X_SKEVM; RoHS: RoHS; Temperature: -40°C+125°C; Tolerance: NA; Voltage: NA; Wattage: NA; Weight: 0.6mg; Datasheet: Y:\MIS_DATABASE\DATASHEETS\ICS\DIGITAL\GATES\SN74LVC1G32XX.PDF
U73 = TPS22810DRVT_WSON6: IC 2.7-18V 3A 79mE ON RESISTANCE LOAD SWITCH WITH THERMAL PROTECTION WSON6; Chkd/date: VASANTHA/300518; Crtd /date: ALVY/290518; Custom_Duty: 15%; Customs_HS_Code: 85423100; Distributor_name: DIGIKEY; Distributor_part_number: 296-46947-1-ND; Footprint Path: Y:\MIS_DATABASE\Library\ALTIUM_TOOL\PCB_FOOTPRINTS\Altium_Footprint_Lib.PcbLib; Height: 0.80MM; Library Path: Y:\MIS_DATABASE\Library\ALTIUM_TOOL\SCHEMATICS_PARTS\MS_MISCPOWER_Library.schlib; Mfr_name: TEXAS INSTRUMENTS; Mistral Part No: 142018050016-R; Package: WSON6; Part_type: ICS\POWER\CONTROL; Project: TI_J7SVB_PCIE_ADD-ON-CARD; RoHS: RoHS; Temperature: -40°C+105°C; Tolerance: NA; Voltage: NA; Wattage: NA; Weight: NA; Datasheet: Y:\MIS_DATABASE\DATASHEETS\ICS\POWER\TPS22810.PDF
U133 = TVS2200_WSON6: IC 22V FLAT-CLAMP SURGE PROTECTION DEVICE WSON6; Chkd/date: MANIRAJA/011021; Crtd /date: ALVY/011021; Custom_Duty: 15%; Customs_HS_Code: 85423100; Distributor_name: DIGIKEY; Distributor_part_number: 296-52187-1-ND; Footprint Path: Y:\MIS_DATABASE\Library\ALTIUM_TOOL\PCB_FOOTPRINTS\Altium_Footprint_Lib.PcbLib; Height: 0.80MM; Library Path: Y:\MIS_DATABASE\Library\ALTIUM_TOOL\SCHEMATICS_PARTS\MS_MISCPOWER_Library.schlib; Mfr_name: TEXAS INSTRUMENTS; Mistral Part No: 142021100001-R; Package: WSON6; Part_type: ICS\POWER; Project: TI_AM62x SKEVM_BRD; RoHS: RoHS; Temperature: -40°C+125°C; Tolerance: NA; Voltage: NA; Wattage: NA; Weight: 12mg; Datasheet: Y:\MIS_DATABASE\DATASHEETS\ICS\POWER\TVS2200.PDF
C201 C218 = CAP: CAP CERAMIC 10uF 10V 20% X5R 0402; Chkd/date: MANIRAJA/150219; Crtd /date: ALVY/150219; Custom_Duty: 15%; Customs_HS_Code: 85322990; Distributor_name: DIGIKEY; Distributor_part_number: 1276-6830-1-ND; Footprint Path: Y:\MIS_DATABASE\Library\ALTIUM_TOOL\PCB_FOOTPRINTS\Altium_Footprint_Lib.PcbLib; Height: 0.90MM; Library Path: Y:\MIS_DATABASE\Library\ALTIUM_TOOL\SCHEMATICS_PARTS\MS_DISCRETE_Library.schlib; Mfr_name: SAMSUNG; Mfr_part_number: CL05A106MP8NUB8; Mistral Part No: 120019020008-R; Package: 0402; Part_type: CAPACITORS\CERAMIC; Project: TI_60GHz-AOP; RoHS: RoHS; Temperature: -55°C+85°C; Tolerance: 20%; Voltage: 10V; Wattage: NA; Weight: NA; Datasheet: Y:\MIS_DATABASE\DATASHEETS\CAPACITORS\CL05A106MP8NUB8.PDF
C206 C212 C219 C436 C475 C487 C492 C510 C513 = CAP: CAP CERAMIC 1uF 10V 20% X5R 0201; Chkd/date: NAVEED/070415; Crtd /date: VASANTHA/230314; Custom_Duty: 15%; Customs_HS_Code: 85322990; Distributor_name: DIGIKEY; Distributor_part_number: 1276-1324-1-ND; Footprint Path: Y:\MIS_DATABASE\Library\ALTIUM_TOOL\PCB_FOOTPRINTS\Altium_Footprint_Lib.PcbLib; Height: 0.35MM; Library Path: Y:\MIS_DATABASE\Library\ALTIUM_TOOL\SCHEMATICS_PARTS\MS_DISCRETE_Library.schlib; Mfr_name: SAMSUNG; Mfr_part_number: CL03A105MP3NSNC; Mistral Part No: 120015030003-R; Package: 0201; Part_type: CAPACITORS\CERAMIC; Project: DUET BOARDS; RoHS: RoHS; Temperature: -55°C+85°C; Tolerance: 20%; Voltage: 10V; Wattage: NA; Weight: 0.17mg; Datasheet: Y:\MIS_DATABASE\DATASHEETS\CAPACITORS\CL03A105MP3NSNC.PDF
C211 C463 C464 C474 C497 = CAP: CAP CERAMIC 4.7uF 6.3V 20% X5R 0201; Chkd/date: ALVY/020522; Crtd /date: TAMILARASU/020522; Custom_Duty: 15%; Customs_HS_Code: 85322990; Distributor_name: NA; Distributor_part_number: NA; Footprint Path: Y:\MIS_DATABASE\Library\ALTIUM_TOOL\PCB_FOOTPRINTS\Altium_Footprint_Lib.PcbLib; Height: 0.33MM; Library Path: Y:\MIS_DATABASE\Library\ALTIUM_TOOL\SCHEMATICS_PARTS\MS_DISCRETE_Library.schlib; Mfr_name: CAL-CHIP; Mfr_part_number: GMC02X5R475M6R3NT; Mistral Part No: 120022050001-R; Package: 0201; Part_type: CAPACITORS\CERAMIC; Project: TI_AM62A_SK_EVM; RoHS: RoHS; Temperature: -55°C+85°C; Tolerance: 20%; Voltage: 6.3V; Wattage: NA; Weight: NA; Datasheet: Y:\MIS_DATABASE\DATASHEETS\CAPACITORS\CALCHIP-GMC-SER.PDF
C438 C456 C459 C467 C472 C479 C480 C485 C491 C495 C496 C501 C508 C512 C517 = CAP: CAP CERAMIC 0.1uF 10V 10% X5R 0201; Chkd/date: MANIRAJA/290421; Crtd /date: ALVY/290421; Custom_Duty: 15%; Customs_HS_Code: 85322990; Distributor_name: DIGIKEY; Distributor_part_number: 1276-1115-1-ND; Footprint Path: Y:\MIS_DATABASE\Library\ALTIUM_TOOL\PCB_FOOTPRINTS\Altium_Footprint_Lib.PcbLib; Height: 0.33MM; Library Path: Y:\MIS_DATABASE\Library\ALTIUM_TOOL\SCHEMATICS_PARTS\MS_DISCRETE_Library.schlib; Mfr_name: SAMSUNG; Mfr_part_number: CL03A104KP3NNNC; Mistral Part No: 120009050017-R; Package: 0201; Part_type: CAPACITORS\CERAMIC; Project: SRMS-SAR_BRD; RoHS: RoHS; Temperature: -55°C+85°C; Tolerance: 10%; Voltage: 10V; Wattage: NA; Weight: 0.33mg; Datasheet: Y:\MIS_DATABASE\DATASHEETS\CAPACITORS\CL03A104KP3NNNC.PDF
FL6 FL9 FL13 FL15 = EMIFILTER_IND: IND FERRITE BEAD CHIP 120E 2A 0402; Chkd/date: MANIRAJA/311221; Crtd /date: ALVY/301221; Custom_Duty: 24%; Customs_HS_Code: 85437099; Distributor_name: NA; Distributor_part_number: NA; Footprint Path: Y:\MIS_DATABASE\Library\ALTIUM_TOOL\PCB_FOOTPRINTS\Altium_Footprint_Lib.PcbLib; Height: 0.55MM; Library Path: Y:\MIS_DATABASE\Library\ALTIUM_TOOL\SCHEMATICS_PARTS\MS_FILTER_Library.schlib; Mfr_name: MURATA; Mfr_part_number: BLM15PX121SZ1B; Mistral Part No: 130021120017-R; Package: 0402; Part_type: INDUCTOR; Project: AM62Q_SKEVM_BRD; RoHS: RoHS; Temperature: -55°C+125°C; Tolerance: 25%; Voltage: NA; Wattage: NA; Weight: 1mg; Datasheet: Y:\MIS_DATABASE\DATASHEETS\DISCRETES\INDUCTORS\BLM-SER.PDF
FL7 FL8 FL14 = EMIFILTER_IND: FERRITE CHIP 26E 6A 0603; Chkd/date: USMAN/020112; Crtd /date: CHAITHANYA/020112; Custom_Duty: 24%; Customs_HS_Code: 85437099; Distributor_name: DIGIKEY; Distributor_part_number: 490-5252-1-ND; Height: 0.75MM; Mfr_name: MURATA; Mfr_part_number: BLM18KG260TN1D; Mistral Part No: 130012010003-R; Package: 0603; Part_type: FILTER; Project: NA10NG; RoHS: RoHS; Temperature: -55°C+125°C; Tolerance: NA; Voltage: NA; Wattage: NA; Weight: NA; Datasheet: Y:\MIS_DATABASE\DATASHEETS\DISCRETES\INDUCTORS\BLM18K-SERIES.PDF
R243 = RESISTOR: RES 0E 1/10W JUMPER 0402; Chkd/date: VASANTHA/061216; Crtd /date: NAVEED/201014; Custom_Duty: 15%; Customs_HS_Code: 85332119; Distributor_name: DIGIKEY; Distributor_part_number: P0.0JCT-ND; Footprint Path: Y:\MIS_DATABASE\Library\ALTIUM_TOOL\PCB_FOOTPRINTS\Altium_Footprint_Lib.PcbLib; Height: 0.40MM; IBISSP_MODLES: VALUE REPEATING 2 TIME; Library Path: Y:\MIS_DATABASE\Library\ALTIUM_TOOL\SCHEMATICS_PARTS\MS_DISCRETE_Library.schlib; Mfr_name: PANASONIC-ECG; Mfr_part_number: ERJ-2GE0R00X; Mistral Part No: 110018030052-R; Package: 0402; Part_type: RESISTORS\FIXED; Project: AEGIS POM; RoHS: RoHS; Temperature: -55°C+155°C; Tolerance: NA; Voltage: NA; Wattage: 1/10W; Weight: 0.8mg; Datasheet: Y:\MIS_DATABASE\DATASHEETS\RESISTORS\PAN-ERJSER_NOV17.PDF
C164 C165 C414 C421 = CAP: CAP CERAMIC 0.1uF 16V 10% X7S AUTO 0201; Alt_Mfr_name: YAGEO AMERICA; Alt_Mfr_part_number: CC0402KRX5R8BB104; Chkd/date: MANIRAJA/110321; Crtd /date: ALVY/110321; Custom_Duty: 15%; Customs_HS_Code: 85322990; Distributor_name: DIGIKEY; Distributor_part_number: 490-GRT033C71C104KE01DTR-ND; Footprint Path: Y:\MIS_DATABASE\Library\ALTIUM_TOOL\PCB_FOOTPRINTS\Altium_Footprint_Lib.PcbLib; Height: 0.33MM; Library Path: Y:\MIS_DATABASE\Library\ALTIUM_TOOL\SCHEMATICS_PARTS\MS_DISCRETE_Library.schlib; Mfr_name: MURATA; Mfr_part_number: GRT033C71C104KE01D; Mistral Part No: 120021030007-R; Package: 0201; Part_type: CAPACITORS\CERAMIC; Project: J7ES_SK_BRD; RoHS: RoHS; Temperature: -55°C+125°C; Tolerance: 10%; Voltage: 16V; Wattage: NA; Weight: 330mg; Datasheet: Y:\MIS_DATABASE\DATASHEETS\CAPACITORS\GRT033C71C104KE01.PDF
R238 = RESISTOR: RES 4.7K 1/20W 5% 0201; Chkd/date: MANIRAJA/200921; Crtd /date: ALVY/200921; Custom_Duty: 15%; Customs_HS_Code: 85332119; Distributor_name: DIGIKEY; Distributor_part_number: 311-4.7KNCT-ND; Footprint Path: Y:\MIS_DATABASE\Library\ALTIUM_TOOL\PCB_FOOTPRINTS\Altium_Footprint_Lib.PcbLib; Height: 0.26MM; Library Path: Y:\MIS_DATABASE\Library\ALTIUM_TOOL\SCHEMATICS_PARTS\MS_DISCRETE_Library.schlib; Mfr_name: YAGEO AMERICA; Mfr_part_number: RC0201JR-074K7L; Mistral Part No: 110021090007-R; Package: 0201; Part_type: RESISTORS\FIXED; Project: TI_AM62x SKEVM_BRD; RoHS: RoHS; Temperature: -55°C+125°C; Tolerance: 5%; Voltage: NA; Wattage: 1/20W; Weight: 0.17mg; Datasheet: Y:\MIS_DATABASE\DATASHEETS\RESISTORS\RCXXXXL-SER_MAR18.PDF
R685 R686 = RESISTOR: RES 100K 1/20W 5% 0201; Chkd/date: MANIRAJA/050517; Crtd /date: MANIRAJA/050517; Custom_Duty: 15%; Customs_HS_Code: 85332119; Distributor_name: DIGIKEY; Distributor_part_number: 311-100KNCT-ND; Footprint Path: Y:\MIS_DATABASE\Library\ALTIUM_TOOL\PCB_FOOTPRINTS\Altium_Footprint_Lib.PcbLib; Height: 0.26MM; Library Path: Y:\MIS_DATABASE\Library\ALTIUM_TOOL\SCHEMATICS_PARTS\MS_DISCRETE_Library.schlib; Mfr_name: YAGEO AMERICA; Mfr_part_number: RC0201JR-07100KL; Mistral Part No: 110009030176-R; Package: 0201; Part_type: RESISTORS\FIXED; Project: GOLDEN-I LITE; RoHS: RoHS; Temperature: -55°C+125°C; Tolerance: 5%; Voltage: NA; Wattage: 1/20W; Weight: 0.17mg; Datasheet: Y:\MIS_DATABASE\DATASHEETS\RESISTORS\RCXXXXL-SER_MAR18.PDF
U32 = TXB0104PWR_TSSOP14: IC 4-BIT BIDIRECTIONAL VOLTAGE-LEVEL TRANSLATOR TSSOP14; Chkd/date: VASANTHA/221216; Crtd /date: USMAN/290609; Custom_Duty: 15%; Customs_HS_Code: 85423100; Distributor_name: DIGIKEY; Distributor_part_number: 296-21929-1-ND; Footprint Path: Y:\MIS_DATABASE\Library\ALTIUM_TOOL\PCB_FOOTPRINTS\Altium_Footprint_Lib.PcbLib; Height: 1.20MM; Library Path: Y:\MIS_DATABASE\Library\ALTIUM_TOOL\SCHEMATICS_PARTS\MS_MISCINTERFACE_Library.schlib; Mfr_name: TEXAS INSTRUMENTS; Mistral Part No: 141009060041-R; Package: TSSOP14; Part_type: ICS\INTERFACE; Project: BUG_BASE-II; RoHS: RoHS; Temperature: -40°C+85°C; Tolerance: NA; Voltage: NA; Wattage: NA; Weight: NA; Datasheet: Y:\MIS_DATABASE\DATASHEETS\ICS\INTERFACE\TXB0104.PDF
U43 U86 = SN74LVC1G11DCKR_SC70-6: IC SINGLE 3-INPUT POSITIVE-AND GATE SON6; Chkd/date: MANIRAJA/270121; Crtd /date: ALVY/270121; Custom_Duty: 15%; Customs_HS_Code: 85423100; Distributor_name: DIGIKEY; Distributor_part_number: 296-30120-1-ND; Footprint Path: Y:\MIS_DATABASE\Library\ALTIUM_TOOL\PCB_FOOTPRINTS\Altium_Footprint_Lib.PcbLib; Height: 0.60MM; Library Path: Y:\MIS_DATABASE\Library\ALTIUM_TOOL\SCHEMATICS_PARTS\MS_GATE_Library.schlib; Mfr_name: TEXAS INSTRUMENTS; Mistral Part No: 141021010013-R; Package: SON6; Part_type: ICS\DIGITAL\GATES; Project: AM64X_SKEVM; RoHS: RoHS; Temperature: -40°C+125°C; Tolerance: NA; Voltage: NA; Wattage: NA; Weight: 33mg; Datasheet: Y:\MIS_DATABASE\DATASHEETS\ICS\DIGITAL\GATES\SN74LVC1G_NOV16.PDF
U47 = AM62D_EVM_SOC_FCBGA484: IC AM62D EVM SoC MICROPROCESSOR FCBGA484; Chkd/date: PRADEEP/010424; Crtd /date: PRADEEP/010424; Custom_Duty: 15%; Customs_HS_Code: 85423100; Distributor_name: NA; Distributor_part_number: NA; Footprint Path: Y:\MIS_DATABASE\Library\ALTIUM_TOOL\PCB_FOOTPRINTS\Altium_Footprint_Lib.PcbLib; Height: 2.65MM; Library Ref: AM62D_EVM_SoC_FCBGA484; Mfr_name: TEXAS INSTRUMENTS; Mistral Part No: 141224040001-R; Package: FCBGA484; Part_type: ICS\DIGITAL\MICROPROCESSOR; Project: AM62D_EVM; RoHS: NA; Temperature: NA; Tolerance: NA; Voltage: NA; Wattage: NA; Weight: NA; Datasheet: Y:\MIS_DATABASE\DATASHEETS\ICS\DIGITAL\MICROCONTROLLER\AM62A_SK_EVM.PDF
R176 R177 R190-R193 R201 R209 R491-R495 R497-R502 R506 = RESISTOR: RES 0E 1/10W JUMPER 0402; Chkd/date: VASANTHA/061216; Crtd /date: NAVEED/201014; Custom_Duty: 15%; Customs_HS_Code: 85332119; Distributor_name: DIGIKEY; Distributor_part_number: P0.0JCT-ND; Footprint Path: Y:\MIS_DATABASE\Library\ALTIUM_TOOL\PCB_FOOTPRINTS\Altium_Footprint_Lib.PcbLib; Height: 0.40MM; IBISSP_MODLES: VALUE REPEATING 2 TIME; Library Path: Y:\MIS_DATABASE\Library\ALTIUM_TOOL\SCHEMATICS_PARTS\MS_DISCRETE_Library.schlib; Mfr_name: PANASONIC-ECG; Mfr_part_number: ERJ-2GE0R00X; Mistral Part No: 110018030052-R; Package: 0402; Part_type: RESISTORS\FIXED; Project: AEGIS POM; RoHS: RoHS; SIGNAL_MODEL: RESISTOR_RES0201_0-5_0E_0E; Temperature: -55°C+155°C; Tolerance: NA; Voltage: NA; Wattage: 1/10W; Weight: 0.8mg; Datasheet: Y:\MIS_DATABASE\DATASHEETS\RESISTORS\PAN-ERJSER_NOV17.PDF
R178 R179 = RESISTOR: RES 22E 1/10W 5% 0402; Chkd/date: VASANTHA/060117; Crtd /date: MAZHAR/120505; Custom_Duty: 15%; Customs_HS_Code: 85332119; Distributor_name: DIGIKEY; Distributor_part_number: P22JCT-ND; Footprint Path: Y:\MIS_DATABASE\Library\ALTIUM_TOOL\PCB_FOOTPRINTS\Altium_Footprint_Lib.PcbLib; Height: 0.40MM; Library Path: Y:\MIS_DATABASE\Library\ALTIUM_TOOL\SCHEMATICS_PARTS\MS_DISCRETE_Library.schlib; Mfr_name: PANASONIC-ECG; Mfr_part_number: ERJ-2GEJ220X; Mistral Part No: 110009030515-R; Package: 0402; Part_type: RESISTORS\FIXED; Project: EPDA_CORE; RoHS: RoHS; Temperature: -55°C+155°C; Tolerance: 5%; Voltage: NA; Wattage: 1/10W; Weight: 0.8mg; Datasheet: Y:\MIS_DATABASE\DATASHEETS\RESISTORS\PAN-ERJSER_NOV17.PDF
R228 R239 R509 R518 R527-R530 R535 R537 = RESISTOR: RES 0E 1/20W 5% 0201; Chkd/date: NAVEED/301214; Crtd /date: MUDDU/120710; Custom_Duty: 15%; Customs_HS_Code: 85332119; Distributor_name: DIGIKEY; Distributor_part_number: 311-0.0NCT-ND; Footprint Path: Y:\MIS_DATABASE\Library\ALTIUM_TOOL\PCB_FOOTPRINTS\Altium_Footprint_Lib.PcbLib; Height: 0.26MM; Library Path: Y:\MIS_DATABASE\Library\ALTIUM_TOOL\SCHEMATICS_PARTS\MS_DISCRETE_Library.schlib; Mfr_name: YAGEO AMERICA; Mfr_part_number: RC0201JR-070RL; Mistral Part No: 110010070067-R; Package: 0201; Part_type: RESISTORS\FIXED; Project: PB_BUGBASE; RoHS: RoHS; SIGNAL_MODEL: RESISTOR_RES0201_0-5_0E_0E; Temperature: -55°C+125°C; Tolerance: 5%; Voltage: NA; Wattage: 1/20W; Weight: 0.17mg; Datasheet: Y:\MIS_DATABASE\DATASHEETS\RESISTORS\RCXXXXL-SER_MAR18.PDF

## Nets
DGND: C164.2 C165.1 C201.2 C206.2 C211.2 C212.2 C218.2 C219.2 C300.1 C302.2 C308.2 C310.2 C326.2 C327.2 C414.1 C421.1 C436.2 C438.2 C456.2 C459.2 C463.2 C464.2 C467.2 C472.2 C474.2 C475.2 C479.2 C480.2 C485.2 C487.2 C491.2 C492.2 C495.2 C496.2 C497.2 C501.2 C508.2 C510.2 C512.2 C513.2 C517.2 C648.2 C654.2 C655.2 D7.2(ANODE) D17.2(ANODE) J24.A1(GND) J24.A12(GND) J24.B1(GND) J24.B12(GND) LD8.1(CATHODE) R238.2 R381.2 R404.2 R685.2 R686.2 R689.2 R690.2 U32.7(GND) U43.2(GND) U71.3(GND) U73.4(GND) U73.7(EP) U86.2(GND) U133.1(GND) U133.2(GND) U133.3(GND) U133.7(GND) ; also on sheet 1 2 3 4 5 6 7 8 9 14 16 17 18 19 20 21 22 31 32 33 34 35 36 37 38 39 40 41 42 43 44 45 46 47 48 49 50 51 52 53 54 55 56 57 58
VBUS_TYPEC1: C326.1 C327.1 C654.1 C655.1 J24.A4(VBUS1) J24.A9(VBUS2) J24.B4(VBUS3) J24.B9(VBUS4) R397.1 TP107.1(TP) U133.4(IN1) U133.5(IN2) U133.6(IN3) ; also on sheet 31 33
VCC1V8_SYS: C164.1 C421.2 R166.1 R242.1 U32.1(VCCA) U43.5(VCC) ; also on sheet 1 2 4 6 7 20 21 22 33 37 38 39 42 43 49 50 52 53 54 55 56 57 58
VCC_3V3_MAIN: FL15.1 ; also on sheet 2 14 32 33 43
VCC_3V3_SYS: C165.2 C414.2 R480.1 U32.14(VCCB) U86.5(VCC) ; also on sheet 1 2 3 6 14 17 18 19 20 22 31 33 37 38 40 41 42 45 46 48 49 50 51 52 53 54 55 56 57 58
VCC_5V0_PG: U86.3(B) ; also on sheet 32
VDD_CORE: FL7.1 FL8.1 FL14.2 ; also on sheet 33 34 35
VDDA_1V8: FL6.1 FL9.1 FL13.1 ; also on sheet 33 34 35
VDDA_1V8_FB1: C456.1 C459.1 C463.1 C464.1 C480.1 C485.1 C501.1 FL13.2 ; also on sheet 34
VDDA_1V8_FB2: C206.1 C467.1 FL6.2 ; also on sheet 34
VDDA_1V8_FB_OSC: C219.1 C508.1 FL9.2 ; also on sheet 34
VDDA_DDR_PLL0: C211.1 C212.1 C491.1 FL14.1 ; also on sheet 34
VDDSHV_SDIO: C201.1 R243.1 ; also on sheet 14 38
 VDDA_CORE_CSI: C472.1 C474.1 C475.1 C479.1 FL7.2 ; also on sheet 34
 VDDA_CORE_USB: C487.1 C495.1 C497.1 FL8.2 ; also on sheet 34
AUDIO_EXT_REFCLK1: R506.2 ; also on sheet 22
AUDIO_EXT_REFCLK1__R: R506.1 U47.K17(GPMC0_WPN)
BOOTMODE0_R: R176.1 U47.N21(GPMC0_AD0) ; also on sheet 9
BOOTMODE1_R: R499.1 U47.N20(GPMC0_AD1) ; also on sheet 9
BOOTMODE2_R: R493.1 U47.N19(GPMC0_AD2) ; also on sheet 9
BOOTMODE3_R: R494.1 U47.N18(GPMC0_AD3) ; also on sheet 9
BOOTMODE4_R: R495.1 U47.N17(GPMC0_AD4) ; also on sheet 9
BOOTMODE5_R: R492.1 U47.P18(GPMC0_AD5) ; also on sheet 9
BOOTMODE6_R: R491.1 U47.P19(GPMC0_AD6) ; also on sheet 9
BOOTMODE7_R: R177.1 U47.P21(GPMC0_AD7) ; also on sheet 9
BOOTMODE8_R: R191.1 U47.P22(GPMC0_AD8) ; also on sheet 9
BOOTMODE9_R: R498.1 U47.R19(GPMC0_AD9) ; also on sheet 9
BOOTMODE10_R: R209.1 U47.R20(GPMC0_AD10) ; also on sheet 9
BOOTMODE11_R: R192.1 U47.R22(GPMC0_AD11) ; also on sheet 9
BOOTMODE12_R: R193.1 U47.T22(GPMC0_AD12) ; also on sheet 9
BOOTMODE13_R: R178.2 U47.R21(GPMC0_AD13) ; also on sheet 9
BOOTMODE14_R: R497.1 U47.T20(GPMC0_AD14) ; also on sheet 9
BOOTMODE15_R: R179.2 U47.T21(GPMC0_AD15) ; also on sheet 9
CAN_IO_3V3: C510.1 C512.1 FL15.2 TP82.1(TP) ; also on sheet 4 33 34
CPLD/EXP2_McASP2_ACLKR: R179.1 ; also on sheet 6 16
CPLD/EXP2_McASP2_ACLKX: R178.1 ; also on sheet 6 22
CPLD/EXP2_McASP2_AFSR: R497.2 ; also on sheet 6 20
CPLD/EXP2_McASP2_AFSX: R193.2 ; also on sheet 6 20
CPLD/EXP2_McASP2_AXR0: R191.2 ; also on sheet 6 22
CPLD/EXP2_McASP2_AXR1: R498.2 ; also on sheet 6 22
CPLD/EXP2_McASP2_AXR3: R192.2 ; also on sheet 6 22
CPLD/EXP2_McASP2_AXR4: R176.2 ; also on sheet 6 22
CPLD/EXP2_McASP2_AXR14: R500.2 ; also on sheet 6 16
CPLD/EXP2_McASP2_AXR15: R190.2 ; also on sheet 6 16
CPLD_OBSCLK0: R209.2 ; also on sheet 22
CPSW_ETH_INTn: U32.11(B3) ; also on sheet 40
CPSW_ETH_INTn_1V8: R205.1 U32.4(A3)
CPSW_RGMII1_RD0: U47.AB16(RGMII1_RD0) ; also on sheet 40
CPSW_RGMII1_RD1: U47.V15(RGMII1_RD1) ; also on sheet 40
CPSW_RGMII1_RD2: U47.W15(RGMII1_RD2) ; also on sheet 40
CPSW_RGMII1_RD3: U47.V14(RGMII1_RD3) ; also on sheet 40
CPSW_RGMII1_RX_DV: U47.AA15(RGMII1_RX_CTL) ; also on sheet 40
CPSW_RGMII1_RXC: U47.AA16(RGMII1_RXC) ; also on sheet 40
CPSW_RGMII1_TD0: R530.2 ; also on sheet 40
CPSW_RGMII1_TD1: R535.2 ; also on sheet 40
CPSW_RGMII1_TD2: R537.2 ; also on sheet 40
CPSW_RGMII1_TD3: R529.2 ; also on sheet 40
CPSW_RGMII1_TX_EN: U47.W16(RGMII1_TX_CTL) ; also on sheet 40
CPSW_RGMII1_TXC: R239.2 ; also on sheet 40
CPSW_RGMII2_RD0: U47.AA21(RGMII2_RD0) ; also on sheet 41
CPSW_RGMII2_RD1: U47.Y20(RGMII2_RD1) ; also on sheet 41
CPSW_RGMII2_RD2: U47.AB21(RGMII2_RD2) ; also on sheet 41
CPSW_RGMII2_RD3: U47.AB20(RGMII2_RD3) ; also on sheet 41
CPSW_RGMII2_RX_DV: U47.W18(RGMII2_RX_CTL) ; also on sheet 41
CPSW_RGMII2_RXC: U47.AA20(RGMII2_RXC) ; also on sheet 41
CPSW_RGMII2_TD0: R509.2 ; also on sheet 41
CPSW_RGMII2_TD1: R518.2 ; also on sheet 41
CPSW_RGMII2_TD2: R527.2 ; also on sheet 41
CPSW_RGMII2_TD3: R528.2 ; also on sheet 41
CPSW_RGMII2_TX_EN: U47.Y19(RGMII2_TX_CTL) ; also on sheet 41
CPSW_RGMII2_TXC: R228.2 ; also on sheet 41
CPSW_RGMII2_TXC_R: R228.1 U47.AB19(RGMII2_TXC)
CPSW_RGMII_TXC_R: R239.1 U47.AB17(RGMII1_TXC)
EXP1_GPIO0_31: U47.N22(GPMC0_CLK) ; also on sheet 54
EXP1_GPIO0_32: U47.L18(GPMC0_ADVN_ALE) ; also on sheet 54
EXP1_GPIO0_33: U47.L17(GPMC0_OEN_REN) ; also on sheet 54
EXP1_GPIO0_34: U47.K19(GPMC0_WEN) ; also on sheet 54
EXP1_GPIO0_35: U47.L19(GPMC0_BE0N_CLE) ; also on sheet 54
EXP1_GPIO0_37: R201.2 ; also on sheet 54
EXP1_GPIO0_37_R: R201.1 U47.R18(GPMC0_WAIT0)
EXP1_GPIO0_38: U47.R17(GPMC0_WAIT1) ; also on sheet 54
EXP1_I2C2_SCL: U47.M22(GPMC0_CSN2) ; also on sheet 54
EXP1_I2C2_SDA: U47.M20(GPMC0_CSN3) ; also on sheet 54
EXP2_McASP2_AXR5: R499.2 ; also on sheet 6
EXP2_McASP2_AXR6: R493.2 ; also on sheet 6
EXP2_McASP2_AXR7: R494.2 ; also on sheet 6
EXP2_McASP2_AXR8: R495.2 ; also on sheet 6
EXP2_McASP2_AXR9: R492.2 ; also on sheet 6
EXP2_McASP2_AXR10: R491.2 ; also on sheet 6
EXP2_McASP2_AXR11: R177.2 ; also on sheet 6
EXP2_McASP2_AXR12: R501.2 ; also on sheet 6
EXP2_McASP2_AXR12_R: R501.1 U47.M18(GPMC0_BE1N)
EXP2_McASP2_AXR13: R502.2 ; also on sheet 6
EXP2_McASP2_AXR13_R: R502.1 U47.K18(GPMC0_DIR)
JTAG_EMU_RSTn: U86.6(C) ; also on sheet 46
LDO_3V3: C300.2 R691.1 U71.5(VCC) ; also on sheet 31
McASP2_AXR14_R: R500.1 U47.M19(GPMC0_CSN0)
McASP2_AXR15_R: R190.1 U47.M21(GPMC0_CSN1)
MCU_PORz: R238.1 R242.2 TP49.1(TP) U43.4(Y) U47.A7(MCU_PORZ)
MCU_RESETSTATz: TP47.1(TP) U47.D14(MCU_RESETSTATZ)
MCU_RESETz: U47.C12(MCU_RESETZ) ; also on sheet 57
MCU_SAFETY_ERRORz_1V8: TP54.1(TP) U32.5(A4) U47.B8(MCU_ERRORN)
MCU_SAFETY_ERRORz_3V3: U32.10(B4) ; also on sheet 33
PMIC_INTn_1V8: R205.2 U47.F17(EXTINTN) ; also on sheet 2
PMIC_POWERGOOD: U86.1(A) ; also on sheet 33
PORT1_15W: R690.1 U71.2(A) ; also on sheet 31
PORT2_15W: R689.1 U71.1(B) ; also on sheet 31
PORz_OUT: U32.12(B2) ; also on sheet 38 40 41 43
PORz_OUT_1V8: R685.1 TP101.1(TP) U32.3(A2) U47.F18(PORZ_OUT) ; also on sheet 6 54
RESETSTATz: U32.13(B1) ; also on sheet 5 37 38 39 40 41 43 49 55 56
RESETSTATZ_1V8: R686.1 TP100.1(TP) U32.2(A1) U47.F19(RESETSTATZ) ; also on sheet 20 22 50
SoC_DVDD3V3: C492.1 C496.1 ; also on sheet 14 34 35
SoC_PORz: R480.2 U43.3(B) U86.4(Y)
SOC_PORz_PB: U43.1(A) ; also on sheet 57
SoC_VDDSHV5_SDIO: C436.1 C438.1 R243.2 ; also on sheet 34
SoC_WARM_RESETZ: U47.E19(RESET_REQZ) ; also on sheet 57
TEST_PORZn: U43.6(C) ; also on sheet 3
USB_TYPEC1_EARTH: C648.1 J24.SH1 J24.SH2 J24.SH3 J24.SH4 R404.1
USBC_CONN1_CC1: D7.1(CATHODE) J24.A5(CC1) ; also on sheet 31
USBC_CONN1_CC2: D17.1(CATHODE) J24.B5(CC2) ; also on sheet 31
VMAIN: C310.1 R395.1 U73.1(VOUT) ; also on sheet 32
VMAIN_EN: LD14.1(CATHODE) R381.1 R382.1 U71.4(Y)
VMAIN_PD: C302.1 U73.6(VIN) ; also on sheet 31
VPP_1V8: C218.1 C513.1 C517.1 ; also on sheet 14 34
N27107689: C308.1 U73.3(CT)
N27107697: R382.2 U73.5(EN/UVLO)
N27107782: R395.2 U73.2(QOD)
N27108105: LD8.2(ANODE) R397.2
N27152136: R530.1 U47.Y17(RGMII1_TD0)
N27152138: R535.1 U47.V16(RGMII1_TD1)
N27152140: R537.1 U47.Y16(RGMII1_TD2)
N27152142: R529.1 U47.AA17(RGMII1_TD3)
N27152150: R509.1 U47.AA19(RGMII2_TD0)
N27152152: R518.1 U47.Y18(RGMII2_TD1)
N27152154: R527.1 U47.AA18(RGMII2_TD2)
N27152156: R528.1 U47.W17(RGMII2_TD3)
N27166782: R166.2 U32.8(OE)
N27856504: LD14.2(ANODE) R691.2

Not connected (* = marked no-connect by the designer): J24 A2(TX1+)* A3(TX1-)* A6(D+_1)* A7(D-_1)* A8(SBU1)* A10(RX2-)* A11(RX2+)* B2(TX2+)* B3(TX2-)* B6(D+_2)* B7(D-_2)* B8(SBU2)* B10(RX1-)* B11(RX1+)*; U32 6(NC1)* 9(NC2)*

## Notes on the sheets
sheet 10
- SOC  RESET - 1
- SOC - RESET
- Pull-down resistor on PORz_OUT is provided to keep the signal
  low until the processor is released from reset during the
  power-up seqence
- LEVEL TRANSLATOR
- SOC POWER ON RESET
- MCU POWER ON RESET
sheet 11
- SOC GPMC
- SOC CPSW3G ETHERNET INTERFACE
- Recommended 0E provision on
  RGMII TXC for signal integrity
- Recommended 0E provision on
  RGMII TXC for signal integrity
sheet 12
- USB TYPE-C POWER CONNECTOR
- POWER INDICATION LED: VBUS_TYPEC1
- Silk: TYPE-C PWR
- LOAD SWITCH FOR VMAIN
- LD14 ON: VBUS_TYPEC1 or VBUS_TYPEC2
  does not meet power delivery requirements
- POWER ERROR
  INDICATION LED
- RED
sheet 13
- SOC POWER SUPPLIES - DECAPS 2
- 3.3V/1.8V MMC1 SUPPLY
- Peripherals - 1.8V Analog SUPPLY
- Peripherals - Core SUPPLY
- VDDA_1V8_CSIRX
- Always ON supply
- VDDA_CORE_CSI
- VDDA_DDR_PLL0
- VPP_1V8
- BLM15PX121SN1D :- 120E
  2A @ 85 deg C
  1.1A @ 125 deg C
